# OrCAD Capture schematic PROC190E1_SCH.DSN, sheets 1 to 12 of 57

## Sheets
1 35. Ethernet PHY PWR SUPPLY: size C; title: ETHERNET PHY POWER SUPPLY; rev: E1
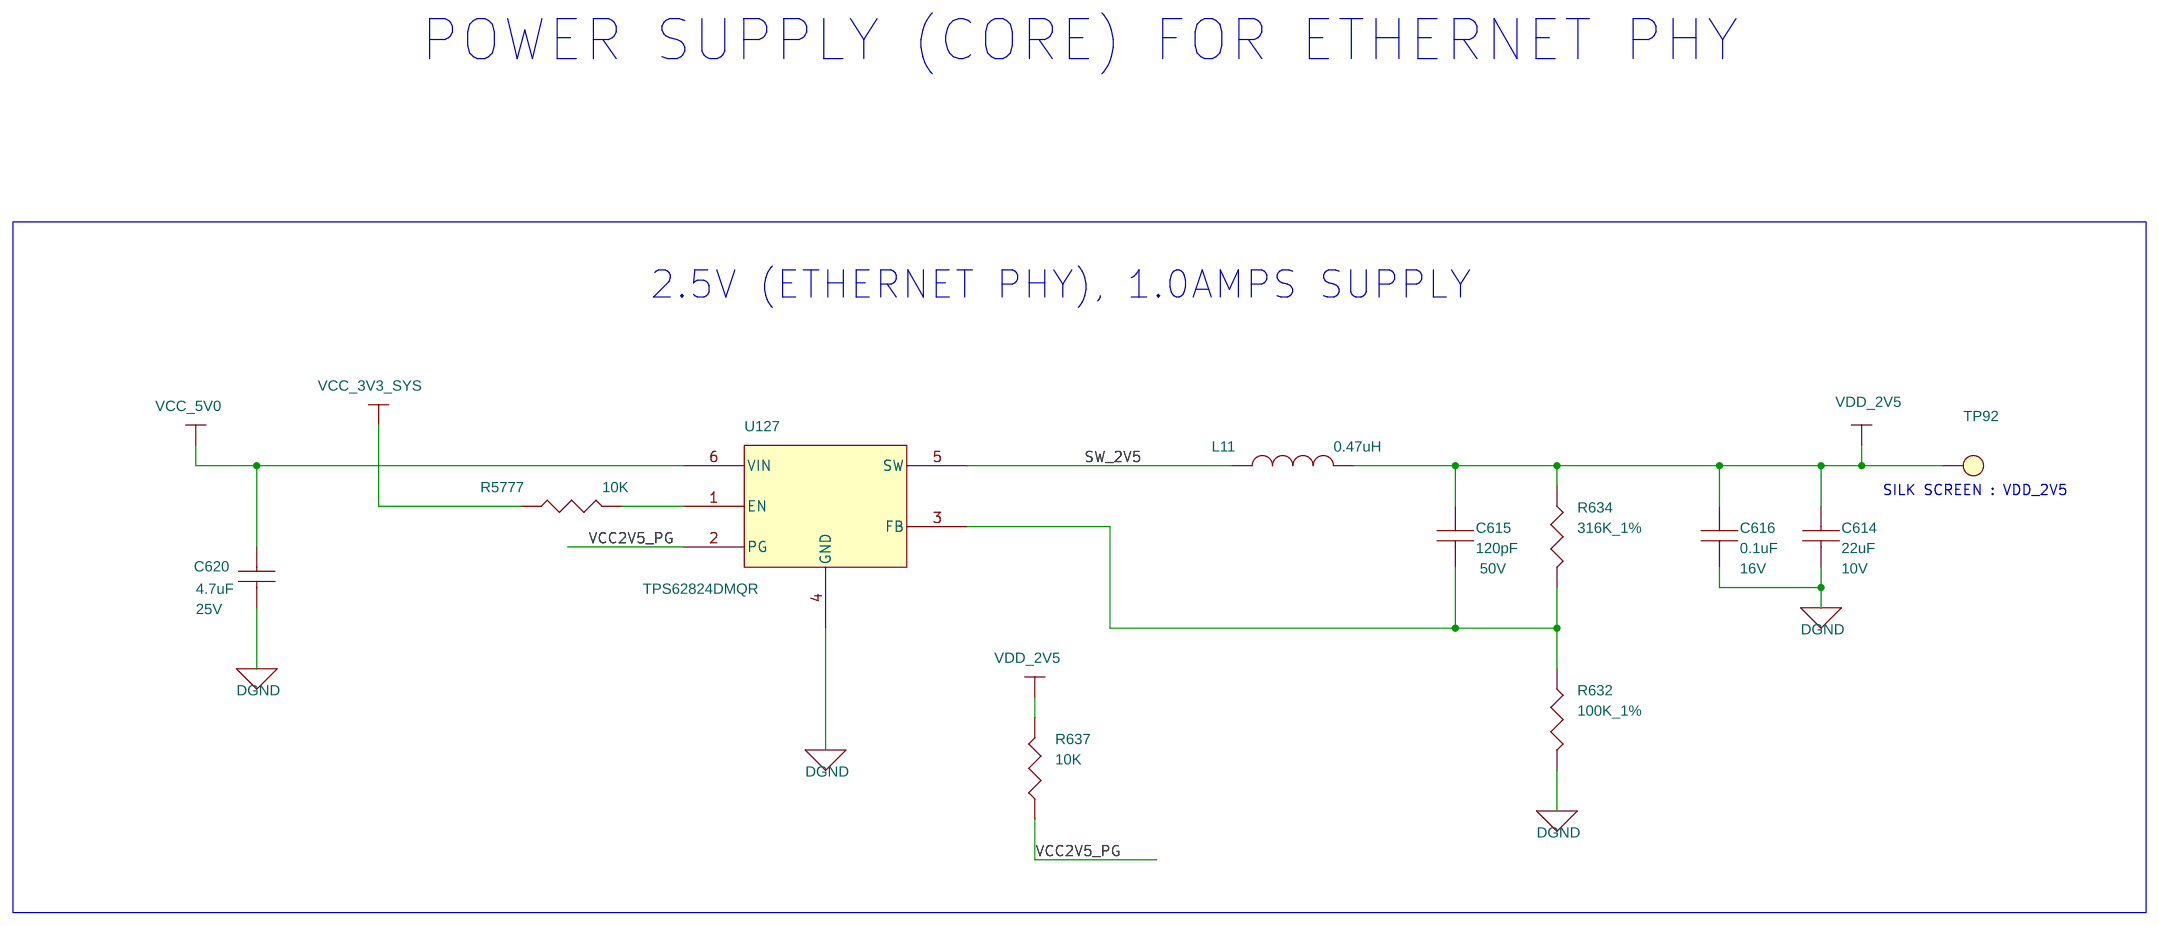
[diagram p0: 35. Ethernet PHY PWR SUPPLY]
2 26. MMC0 INTERFACE SELECTION: size C; title: MMC0 INTERFACE
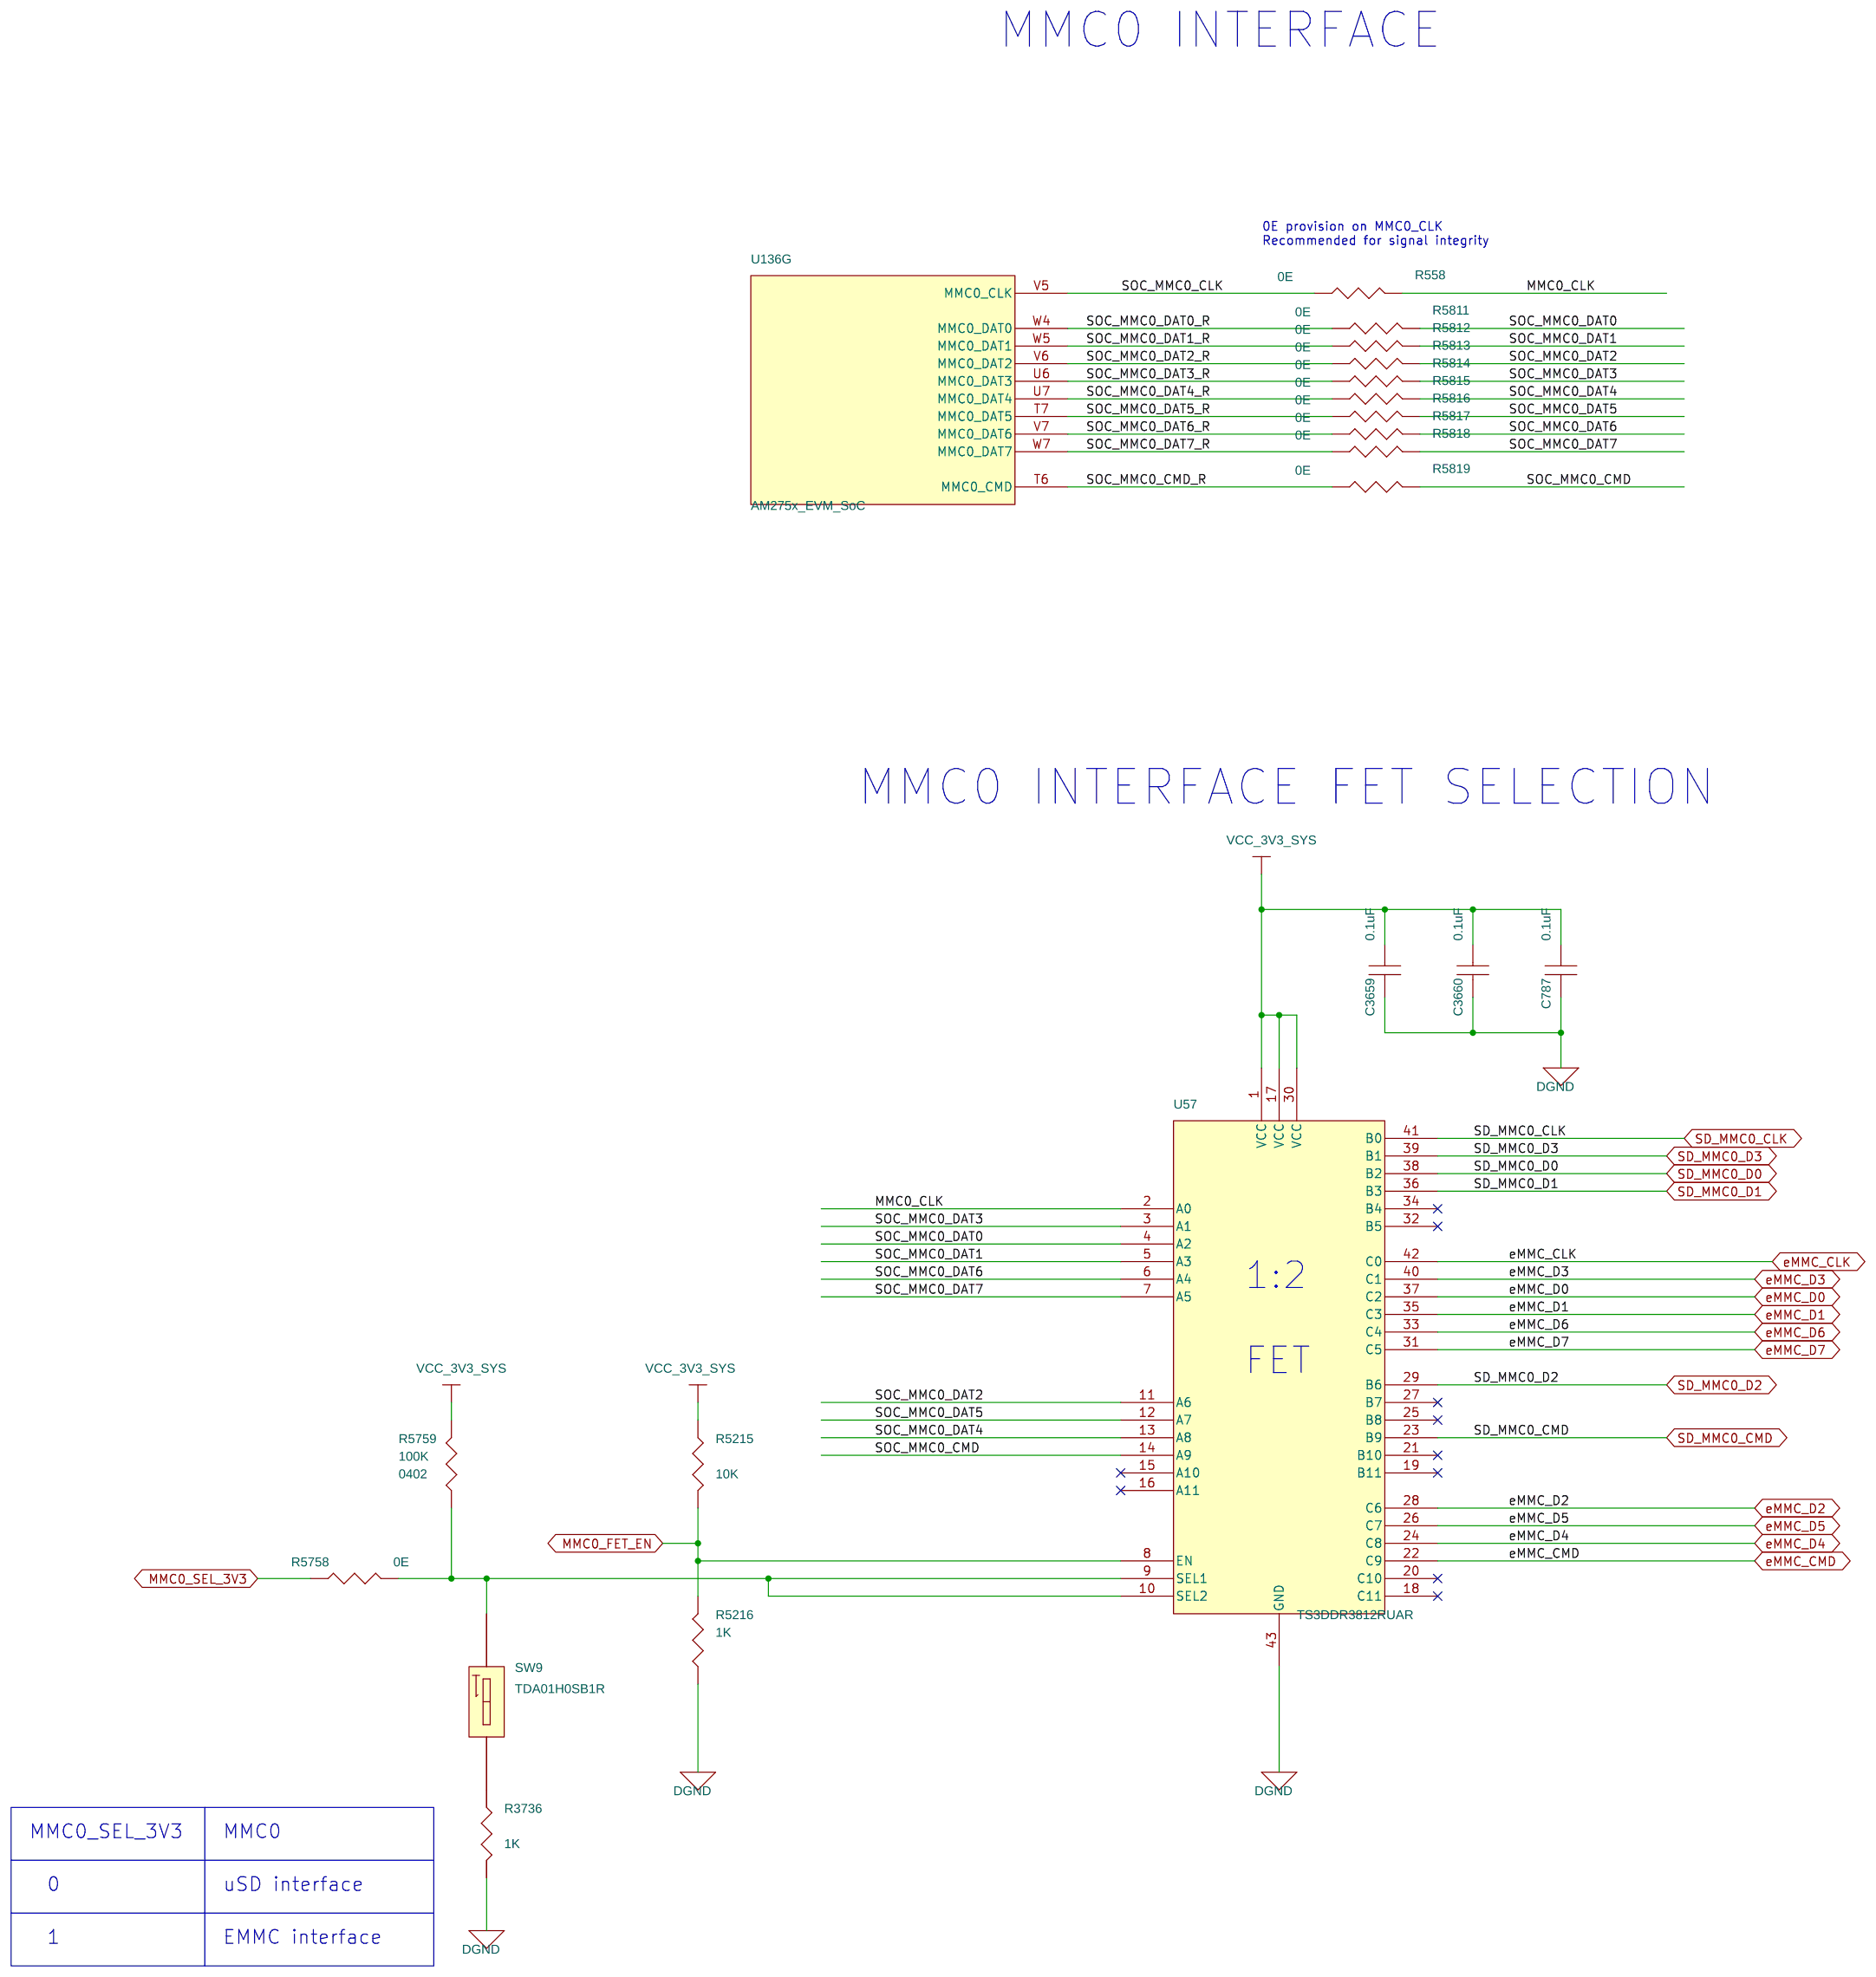
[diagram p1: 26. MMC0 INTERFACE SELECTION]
3 01. TABLE OF CONTENTS: title: TABLE OF CONTENTS
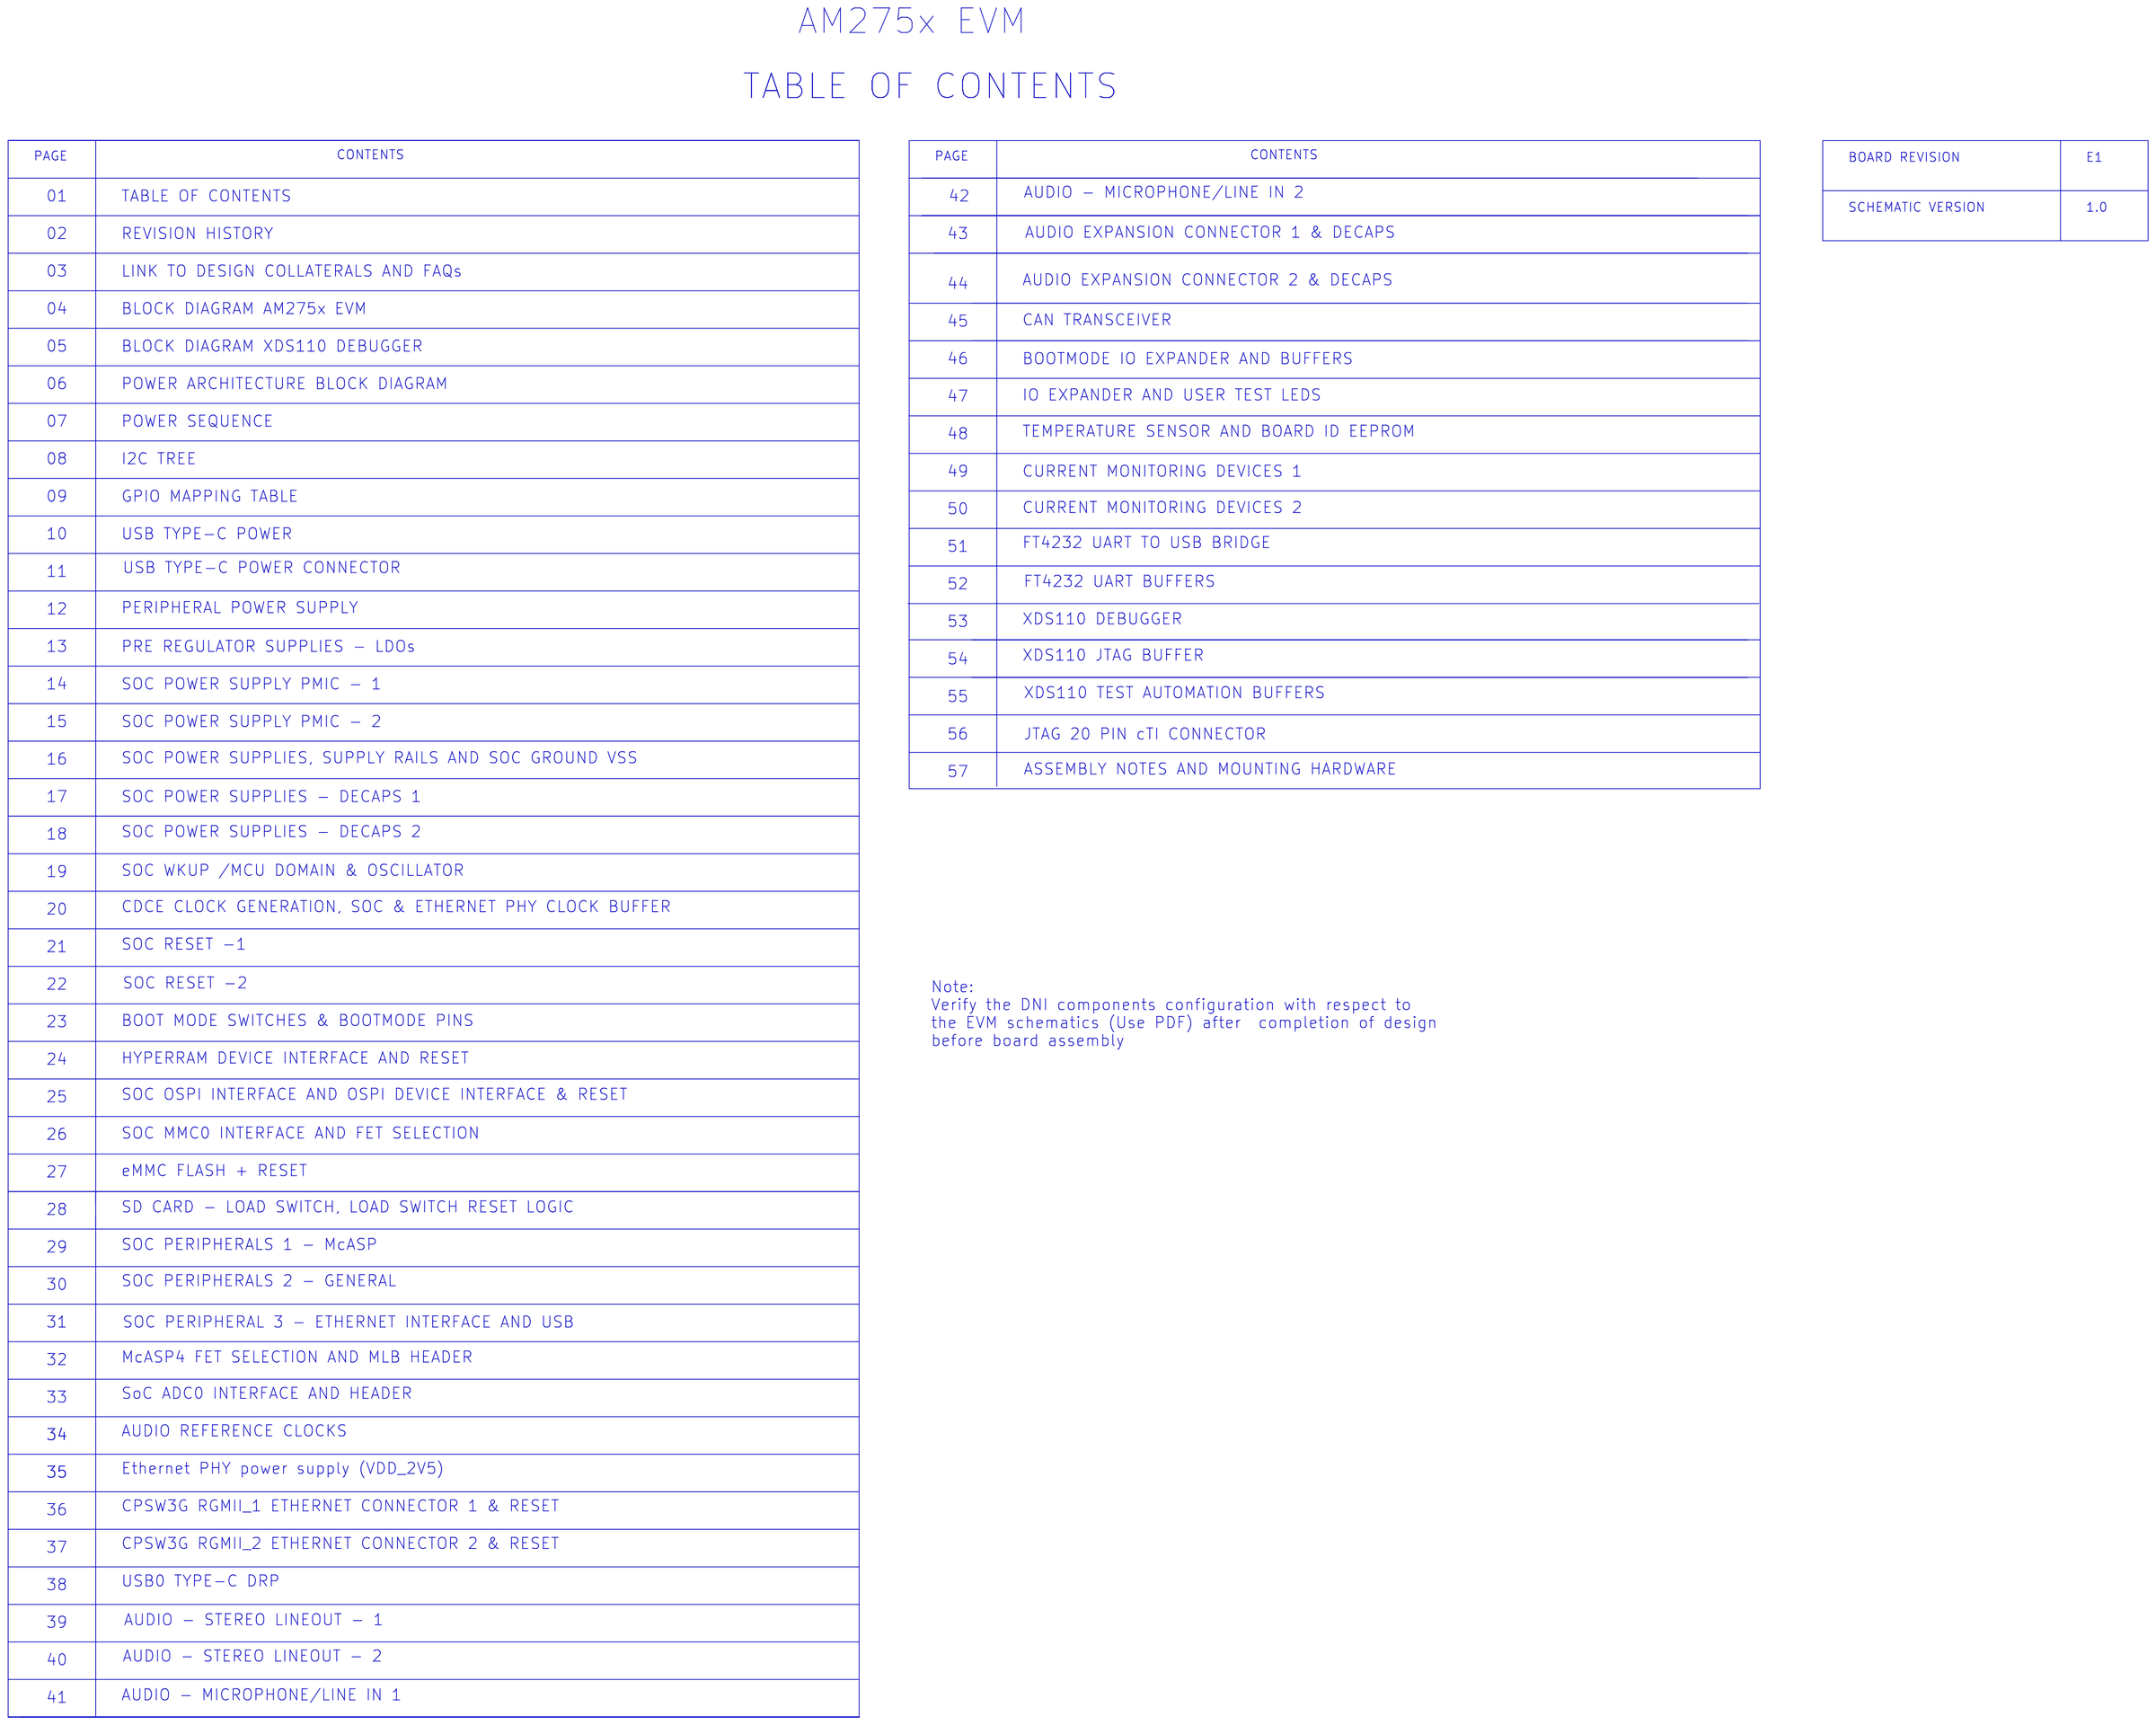
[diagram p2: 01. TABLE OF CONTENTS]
4 02. REVISION HISTORY: title: REVISION HISTORY
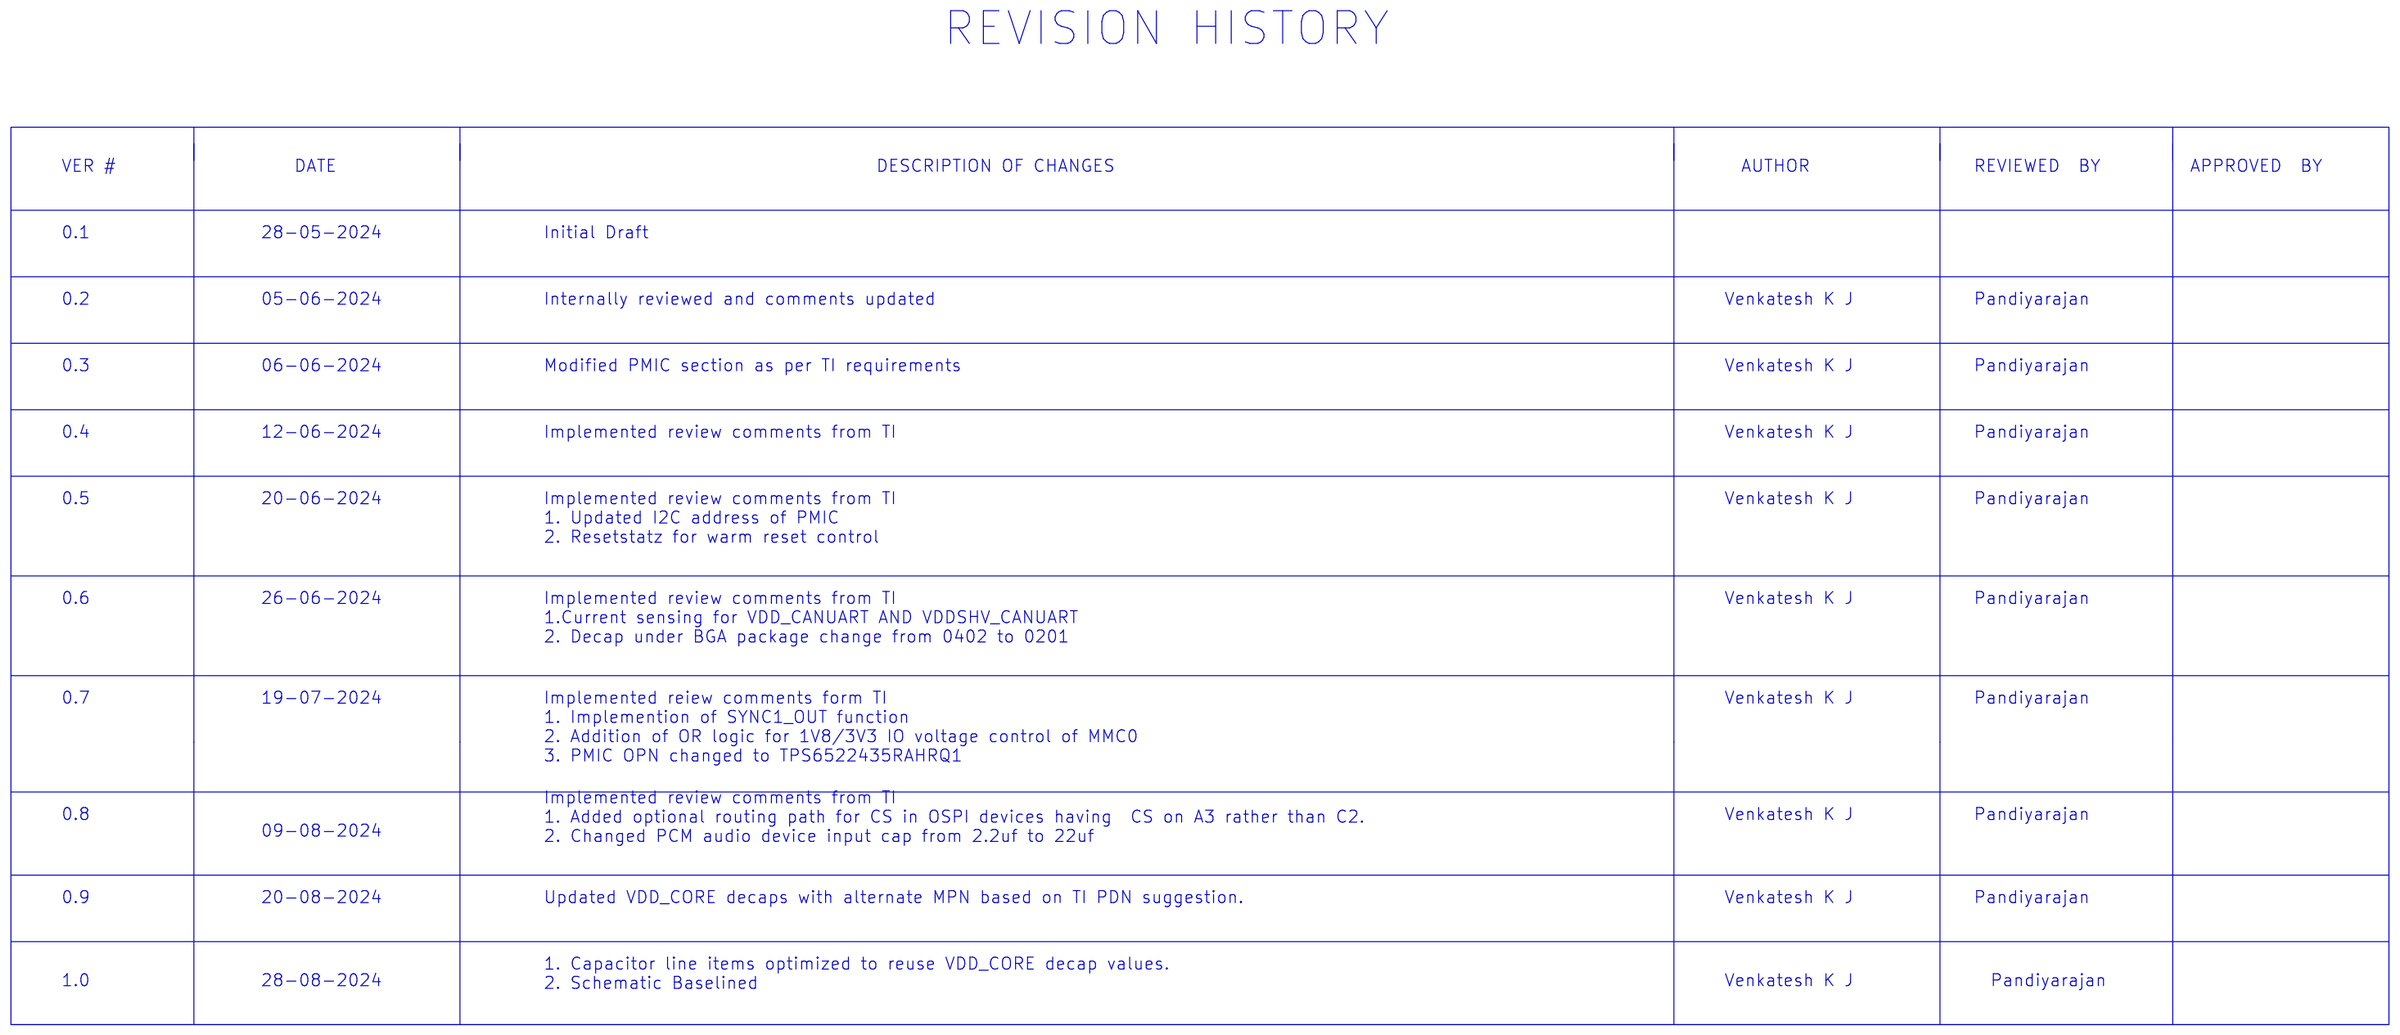
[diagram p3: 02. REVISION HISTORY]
5 03. KEY COLLATERAL REFERENCES: title: LINK TO DESIGN COLLATERALS
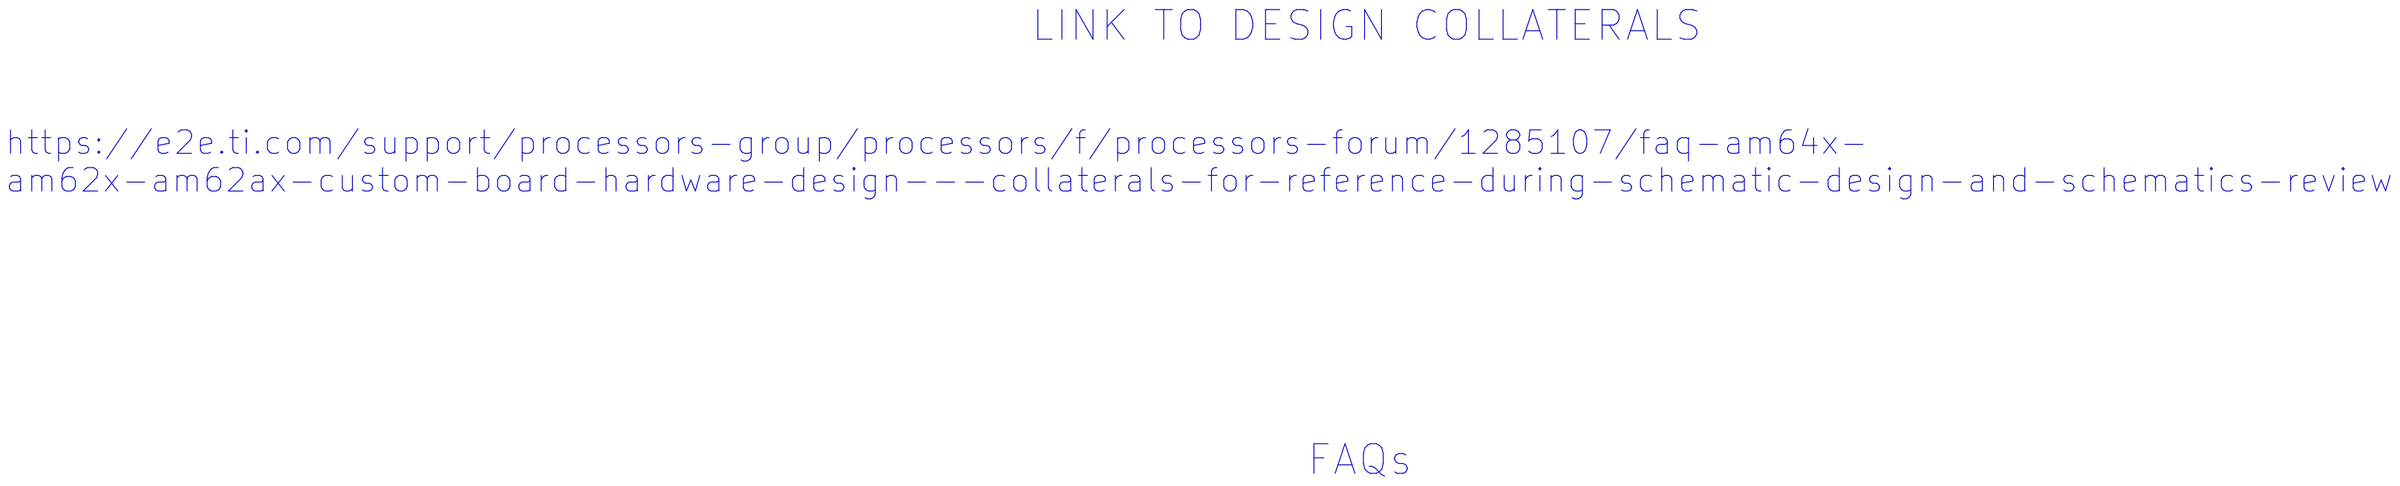
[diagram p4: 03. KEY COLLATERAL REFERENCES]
6 04. BLOCK DGM AM275 EVM: title: BLOCK DIAGRAM AM62D_ SKEVM
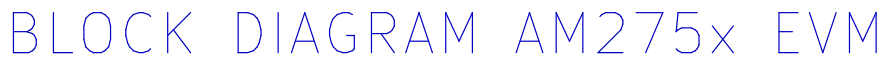
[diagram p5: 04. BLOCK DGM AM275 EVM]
7 05. BLOCK DIAGRAM_XDS110: title: BLOCK DIAGRAM_XDS110
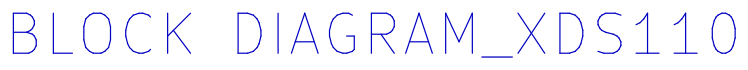
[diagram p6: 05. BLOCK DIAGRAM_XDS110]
8 06. POWER BLOCK DGM: title: POWER ARCHITECTURE BLOCK DIAGRAM
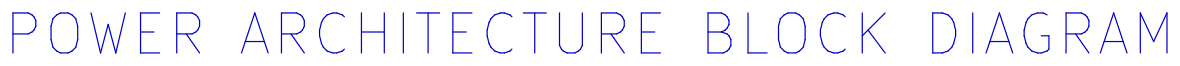
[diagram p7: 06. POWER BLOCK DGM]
9 07. POWER SEQUENCE: title: POWER SEQUENCE
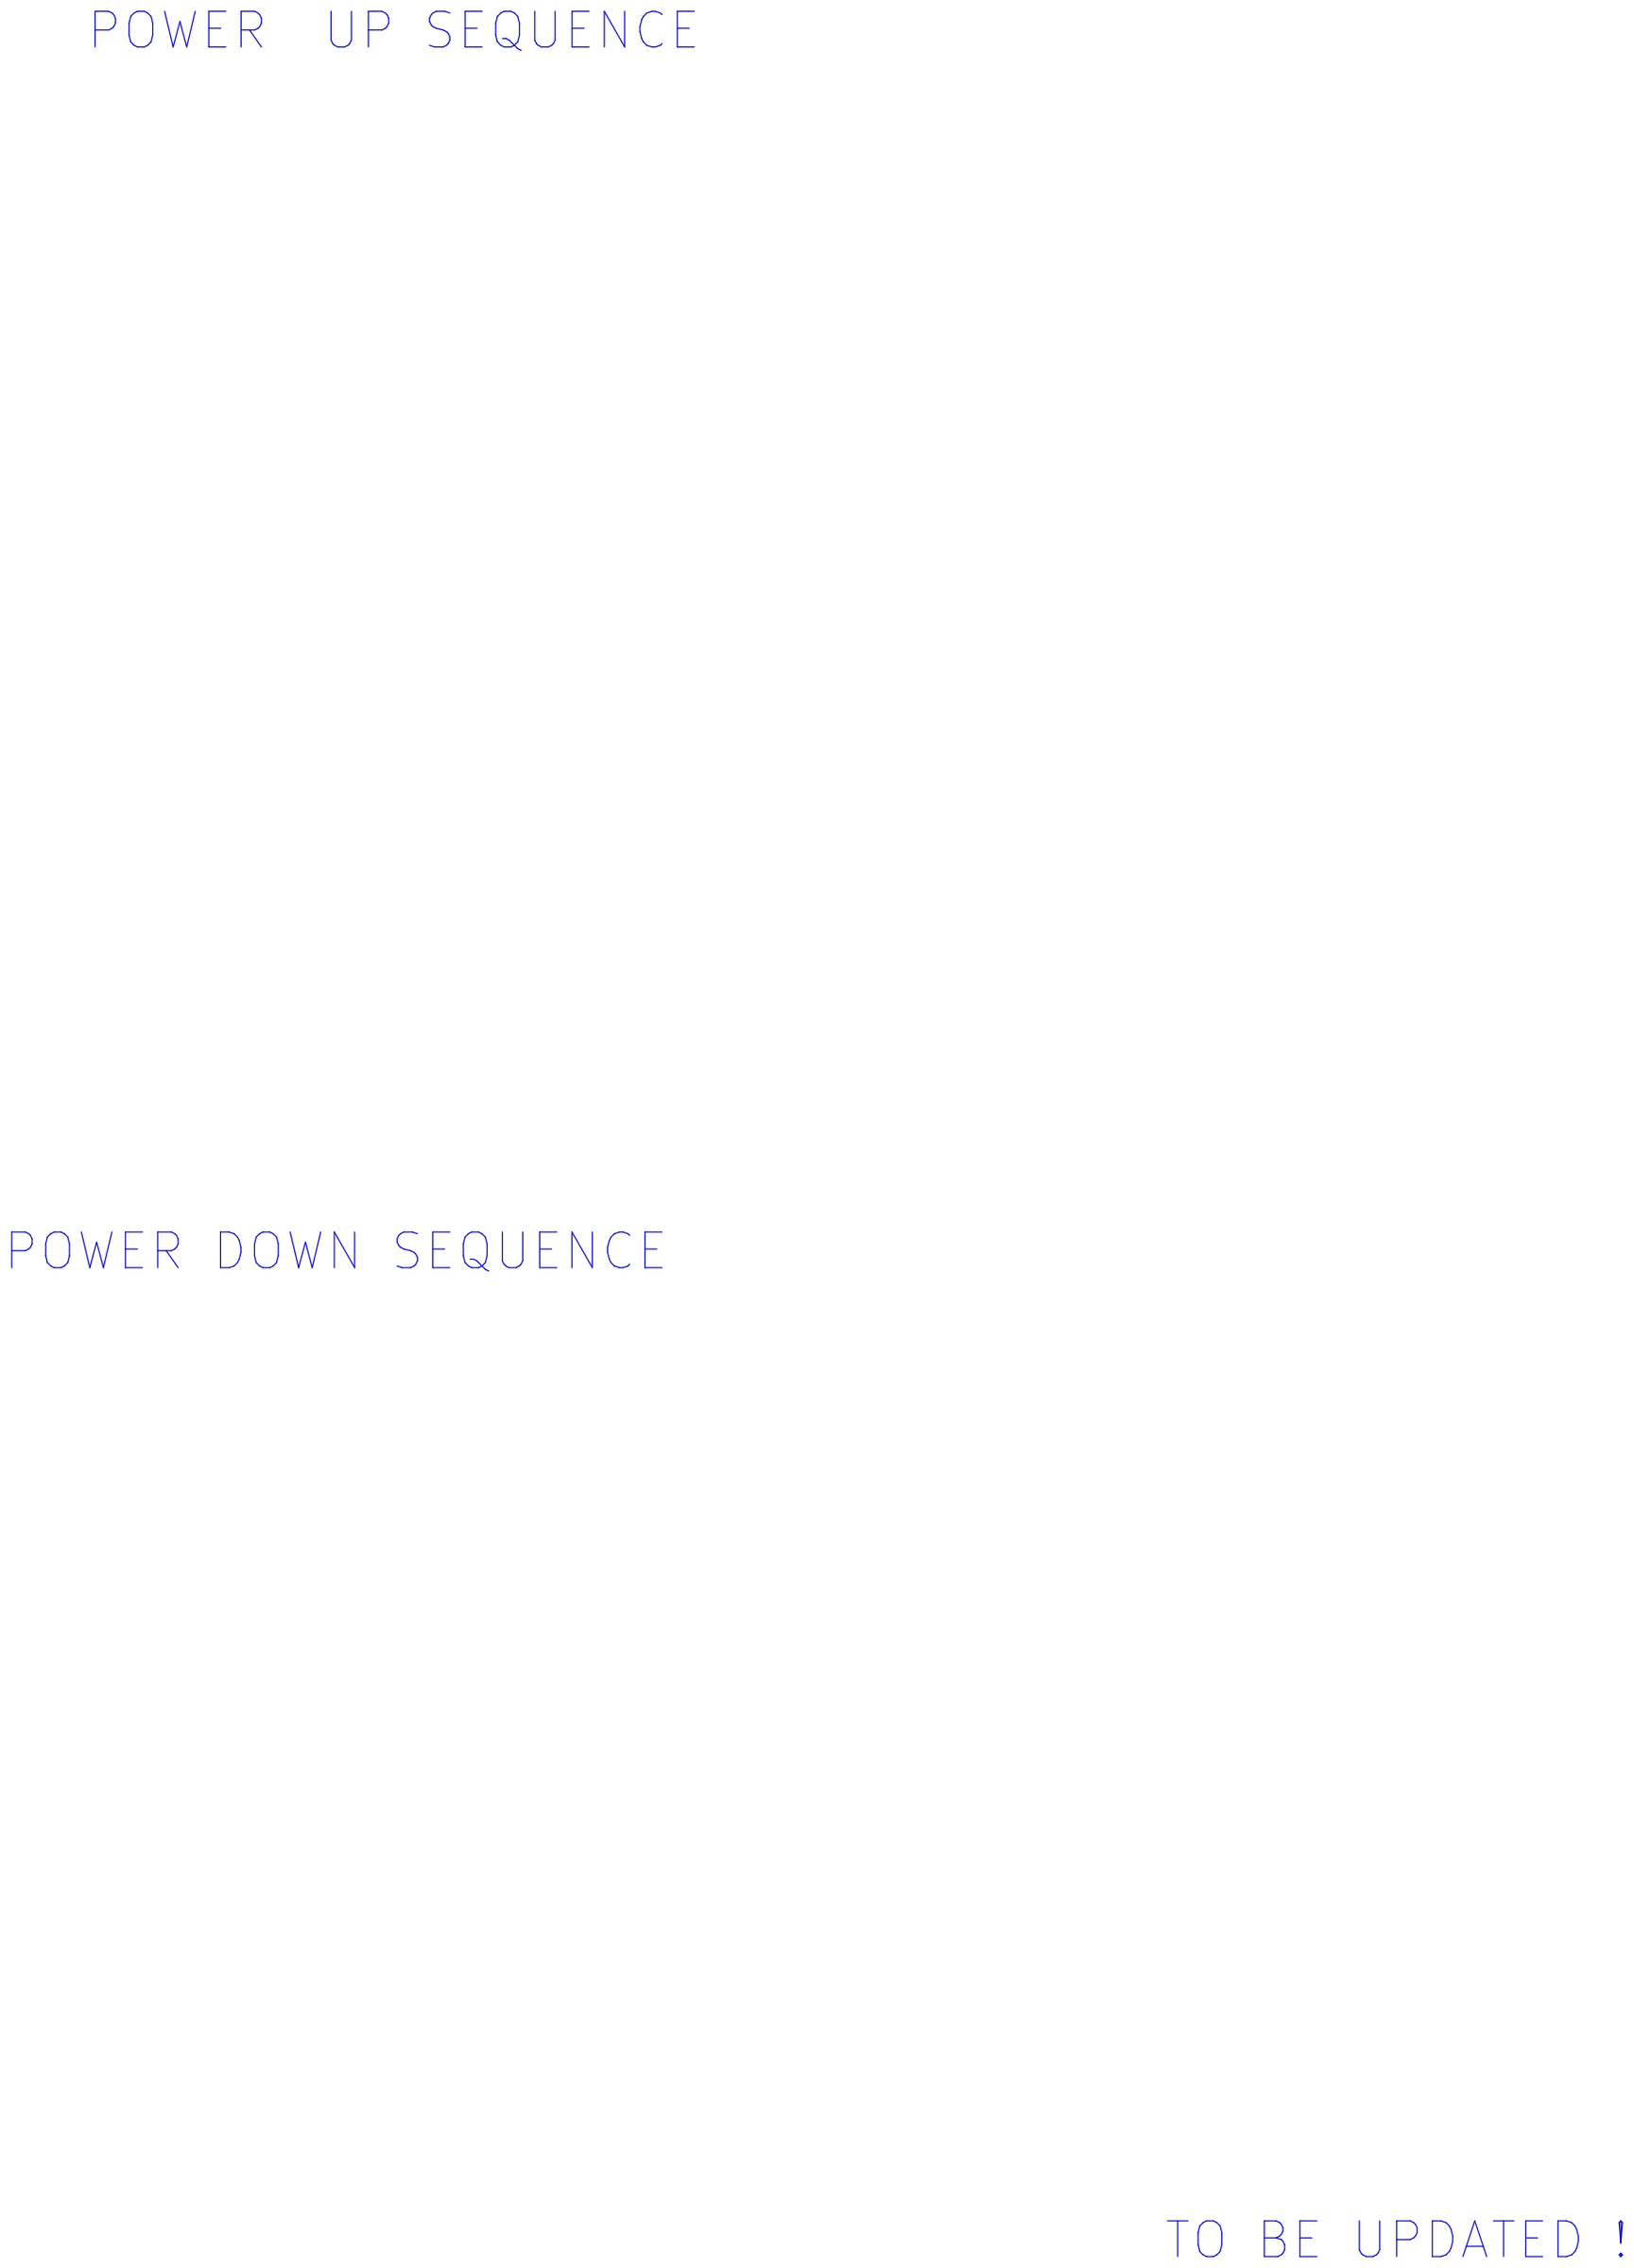
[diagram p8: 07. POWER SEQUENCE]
10 08. I2C TREE: title: I2C TREE
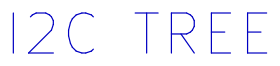
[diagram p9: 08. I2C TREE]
11 09. GPIO MAPPING TABLE: title: GPIO MAPPING TABLE
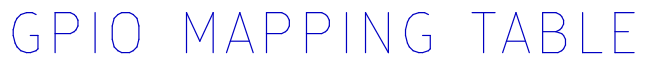
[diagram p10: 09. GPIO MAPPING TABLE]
12 10. USB TYPE-C POWER: size C; title: USB TYPE-C POWER
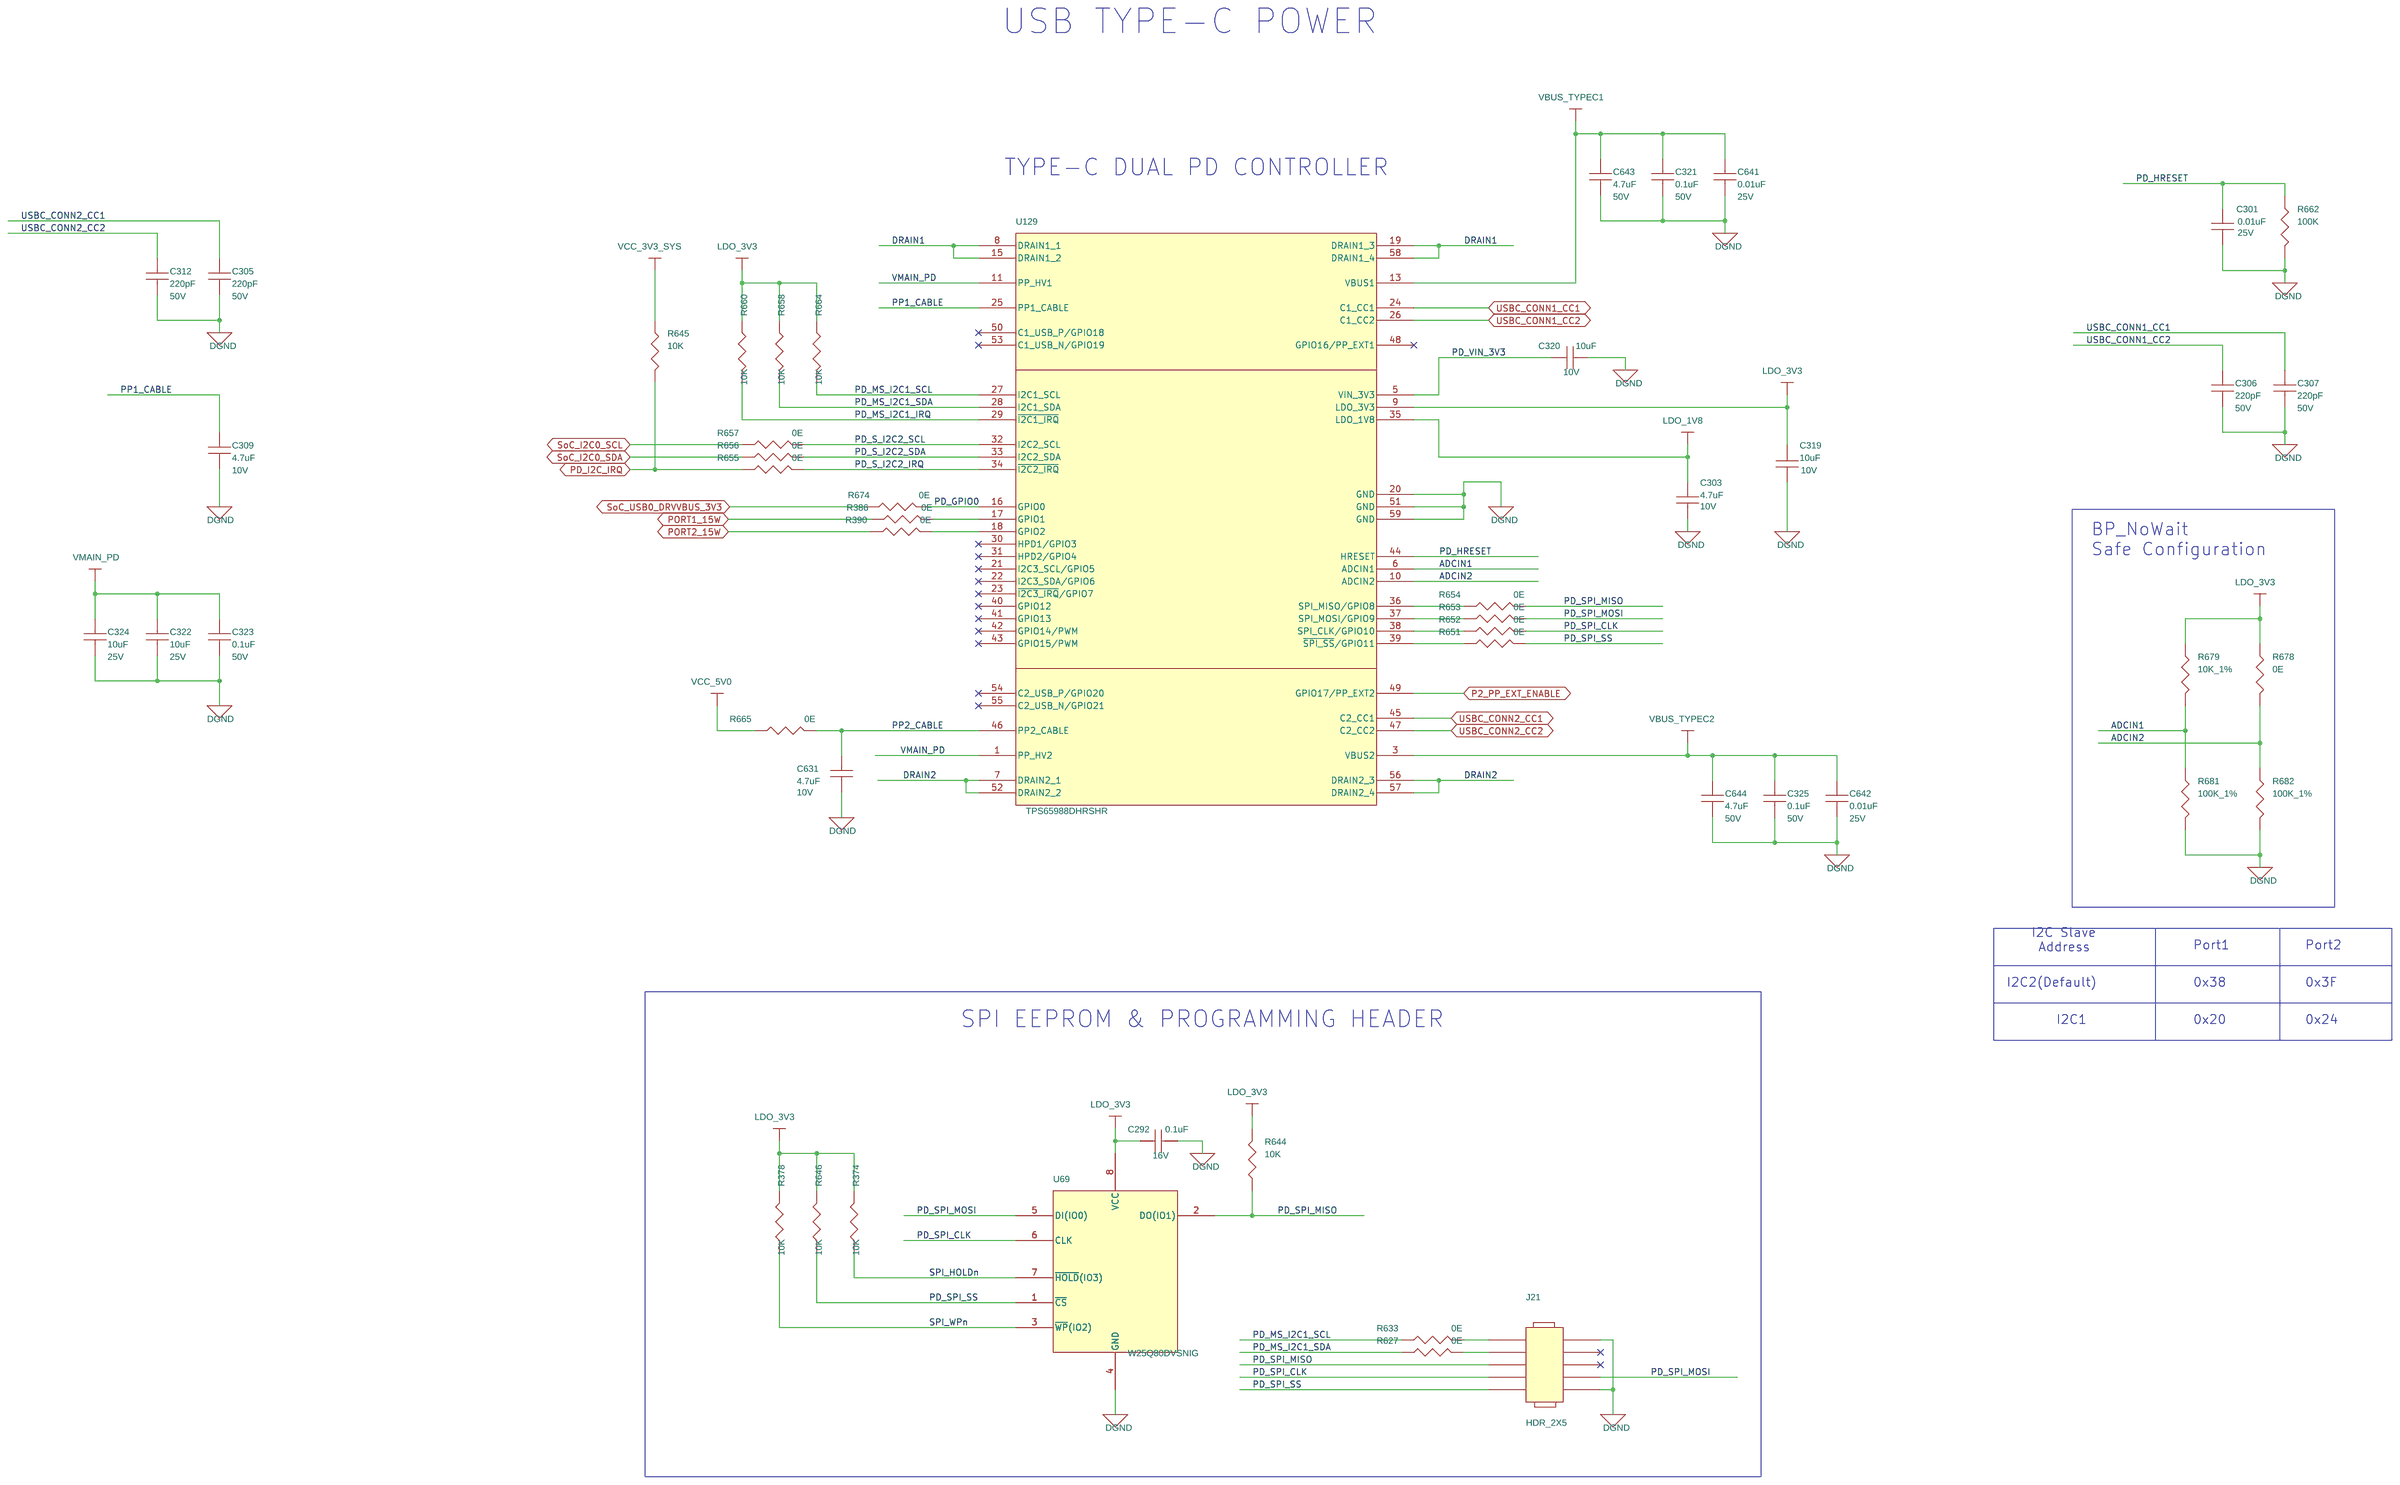
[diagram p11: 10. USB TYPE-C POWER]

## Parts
sheet 10. USB TYPE-C POWER
C292  0.1uF  [CAP0201_0-5]
C301  0.01uF  [CAP0201_0-5]
C303  4.7uF  [CAP0402_0-75]
C305  220pF  [CAP0402_0-75]
C306  220pF  [CAP0402_0-75]
C307  220pF  [CAP0402_0-75]
C309  4.7uF  [CAP0402_0-75]
C312  220pF  [CAP0402_0-75]
C319  10uF  [CAP0402_0-75]
C320  10uF  [CAP0402_0-75]
C321  0.1uF  [CAP0402_0-75]
C322  10uF  [CAP0603_1]
C323  0.1uF  [CAP0402_0-75]
C324  10uF  [CAP0603_1]
C325  0.1uF  [CAP0402_0-75]
C631  4.7uF  [CAP0402_0-75]
C641  0.01uF  [CAP0201_0-5]
C642  0.01uF  [CAP0201_0-5]
C643  4.7uF  [CAP0805_1-5]
C644  4.7uF  [CAP0805_1-5]
J21  HDR_2X5  [HDR_2X5_PEC05DAAN_S_T_8-6]
R374  10K  [RES0201_0-5]
R378  10K  [RES0201_0-5]
R386  0E  [RES0201_0-5]
R390  0E  [RES0201_0-5]
R627  0E  [RES0201_0-5]
R633  0E  [RES0201_0-5]
R644  10K  [RES0201_0-5]
R645  10K  [RES0201_0-5]
R646  10K  [RES0201_0-5]
R651  0E  [RES0201_0-5]
R652  0E  [RES0201_0-5]
R653  0E  [RES0201_0-5]
R654  0E  [RES0201_0-5]
R655  0E  [RES0201_0-5]
R656  0E  [RES0201_0-5]
R657  0E  [RES0201_0-5]
R658  10K  [RES0201_0-5]
R660  10K  [RES0201_0-5]
R662  100K  [RES0201_0-5]
R664  10K  [RES0201_0-5]
R665  0E  [RES0402_0-5]
R674  0E  [RES0201_0-5]
R678  0E  [RES0201_0-5]
R679  10K_1%  [RES0201_0-5]
R681  100K_1%  [RES0402_0-5]
R682  100K_1%  [RES0402_0-5]
U69  W25Q80DVSNIG  [SOIC8_1-8]
U129  TPS65988DHRSHR  [VQFN56_TPS65987D_280X280_1]
sheet 19. SOC WKUP & OSC
U136  AM275x_EVM_SoC  [BGA361_31-49_630X630_1-5]  (sections A,B,C,D,E,F,G,H,I,J,K,L,M,N)
sheet 26. MMC0 INTERFACE SELECTION
C787  0.1uF  [CAP0402_0-75]
C3659  0.1uF  [CAP0402_0-75]
C3660  0.1uF  [CAP0402_0-75]
R558  0E  [RES0402_0-5]
R3736  1K  [RES0201_0-5]
R5215  10K  [RES0201_0-5]
R5216  1K  [RES0201_0-5]
R5758  0E  [RES0201_0-5]
R5759  100K  [RES0402_0-5]
R5811  0E  [RES0402_0-5]
R5812  0E  [RES0402_0-5]
R5813  0E  [RES0402_0-5]
R5814  0E  [RES0402_0-5]
R5815  0E  [RES0402_0-5]
R5816  0E  [RES0402_0-5]
R5817  0E  [RES0402_0-5]
R5818  0E  [RES0402_0-5]
R5819  0E  [RES0402_0-5]
SW9  TDA01H0SB1R  [SW_TDA01H0S_240X90_SMD_2-3]
U57  TS3DDR3812RUAR  [TQFN42_19-68_140X360_0-8]
sheet 35. Ethernet PHY PWR SUPPLY
C614  22uF  [CAP0603_1]
C615  120pF  [CAP0201_0-5]
C616  0.1uF  [CAP0201_0-5]
C620  4.7uF  [CAP0603_1]
L11  0.47uH  [IND0806_1-2]
R632  100K_1%  [RES0402_0-5]
R634  316K_1%  [RES0402_0-5]
R637  10K  [RES0201_0-5]
R5777  10K  [RES0201_0-5]
TP92  TP20_SMD  [TP20_SMD]
U127  TPS62824DMQR  [VSONHR6_TPS62826_60X60_1]

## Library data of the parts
C292 C616 = CAP: CAP CERAMIC 0.1uF 16V 10% X7S AUTO 0201; Chkd/date: MANIRAJA/110321; Crtd /date: ALVY/110321; Custom_Duty: 15%; Customs_HS_Code: 85322990; Distributor_name: DIGIKEY; Distributor_part_number: 490-GRT033C71C104KE01DTR-ND; Footprint Path: Y:\MIS_DATABASE\Library\ALTIUM_TOOL\PCB_FOOTPRINTS\Altium_Footprint_Lib.PcbLib; Height: 0.33MM; Library Path: Y:\MIS_DATABASE\Library\ALTIUM_TOOL\SCHEMATICS_PARTS\MS_DISCRETE_Library.schlib; Mfr_name: MURATA; Mfr_part_number: GRT033C71C104KE01D; Mistral Part No: 120021030007-R; Package: 0201; Part_type: CAPACITORS\CERAMIC; Project: J7ES_SK_BRD; RoHS: RoHS; Temperature: -55°C+125°C; Tolerance: 10%; Voltage: 16V; Wattage: NA; Weight: 330mg; Datasheet: Y:\MIS_DATABASE\DATASHEETS\CAPACITORS\GRT033C71C104KE01.PDF
C301 C641 C642 = CAP: CAP CERAMIC 0.01uF 25V 10% X5R AUTO 0201; Chkd/date: MANIRAJA/311221; Crtd /date: ALVY/301221; Custom_Duty: 15%; Customs_HS_Code: 85322990; Distributor_name: MOUSER; Distributor_part_number: 81-GRT033R61E103KE1D; Footprint Path: Y:\MIS_DATABASE\Library\ALTIUM_TOOL\PCB_FOOTPRINTS\Altium_Footprint_Lib.PcbLib; Height: 0.33MM; Library Path: Y:\MIS_DATABASE\Library\ALTIUM_TOOL\SCHEMATICS_PARTS\MS_DISCRETE_Library.schlib; Mfr_name: MURATA; Mfr_part_number: GRT033R61E103KE01D; Mistral Part No: 120021120019-R; Package: 0201; Part_type: CAPACITORS\CERAMIC; Project: AM62Q_SKEVM_BRD; RoHS: RoHS; Temperature: -55°C+85°C; Tolerance: 10%; Voltage: 25V; Wattage: NA; Weight: 0.33mg; Datasheet: Y:\MIS_DATABASE\DATASHEETS\CAPACITORS\GRT033R61E103KE01.PDF
C303 C309 C631 = CAP: CAP CERAMIC 4.7uF 10V 20% X5R AUTO 0402; Chkd/date: MANIRAJA/250221; Crtd /date: ALVY/240221; Custom_Duty: 15%; Customs_HS_Code: 85322990; Distributor_name: MOUSER; Distributor_part_number: 81-GRT155R61A475ME13; Footprint Path: Y:\MIS_DATABASE\Library\ALTIUM_TOOL\PCB_FOOTPRINTS\Altium_Footprint_Lib.PcbLib; Height: 0.65MM; Library Path: Y:\MIS_DATABASE\Library\ALTIUM_TOOL\SCHEMATICS_PARTS\MS_DISCRETE_Library.schlib; Mfr_name: MURATA; Mfr_part_number: GRT155R61A475ME13D; Mistral Part No: 120021020032-R; Package: 0402; Part_type: CAPACITORS\CERAMIC; Project: TI_DRA821 SK EVM BRD; RoHS: RoHS; Temperature: -55°C+85°C; Tolerance: 20%; Voltage: 10V; Wattage: NA; Weight: 1.5mg; Datasheet: Y:\MIS_DATABASE\DATASHEETS\CAPACITORS\GRT155R61A475ME13.PDF
C305-C307 C312 = CAP: CAP CERAMIC 220pF 50V 5% C0G(NP0) AUTO 0402; Chkd/date: PRADEEP/130623; Crtd /date: PRADEEP/130623; Custom_Duty: 15%; Customs_HS_Code: 85322990; Distributor_name: NA; Distributor_part_number: NA; Footprint Path: Y:\MIS_DATABASE\Library\ALTIUM_TOOL\PCB_FOOTPRINTS\Altium_Footprint_Lib.PcbLib; Height: 0.55MM; Library Path: Y:\MIS_DATABASE\Library\ALTIUM_TOOL\SCHEMATICS_PARTS\MS_DISCRETE_Library.schlib; Mfr_name: MURATA; Mfr_part_number: GRT1555C1H221JA02; Mistral Part No: 120022060024-R; Package: 0402; Part_type: CAPACITORS\CERAMIC; Project: AM62P_SK; RoHS: RoHS; Temperature: -55°C+125°C; Tolerance: 5%; Voltage: 50V; Wattage: NA; Weight: 3.1mg; Datasheet: Y:\MIS_DATABASE\DATASHEETS\CAPACITORS\GRT1555C1H221JA02.PDF
C319 C320 = CAP: CAP CERAMIC 10uF 10V 20% X5R 0402; Chkd/date: PRADEEP/130623; Crtd /date: PRADEEP/130623; Custom_Duty: 15%; Customs_HS_Code: 85322990; Distributor_name: NA; Distributor_part_number: NA; Footprint Path: Y:\MIS_DATABASE\Library\ALTIUM_TOOL\PCB_FOOTPRINTS\Altium_Footprint_Lib.PcbLib; Height: 0.55MM; Library Path: Y:\MIS_DATABASE\Library\ALTIUM_TOOL\SCHEMATICS_PARTS\MS_DISCRETE_Library.schlib; Mfr_name: MURATA; Mfr_part_number: GRM155R61A106ME18; Mistral Part No: 120022060018-R; Package: 0402; Part_type: CAPACITORS\CERAMIC; Project: AM62P_SK; RoHS: RoHS; Temperature: -55°C+85°C; Tolerance: 20%; Voltage: 10V; Wattage: NA; Weight: 6mg; Datasheet: Y:\MIS_DATABASE\DATASHEETS\CAPACITORS\MURATA-GXX-SER_NOV17.PDF
C321 C323 C325 = CAP: CAP CERAMIC 0.1uF 50V 10% X7R AUTO 0402; Chkd/date: MANIRAJA/250221; Crtd /date: ALVY/240221; Custom_Duty: 15%; Customs_HS_Code: 85322990; Distributor_name: MOUSER; Distributor_part_number: 81-GRT155R71H104KE1D; Footprint Path: Y:\MIS_DATABASE\Library\ALTIUM_TOOL\PCB_FOOTPRINTS\Altium_Footprint_Lib.PcbLib; Height: 0.55MM; Library Path: Y:\MIS_DATABASE\Library\ALTIUM_TOOL\SCHEMATICS_PARTS\MS_DISCRETE_Library.schlib; Mfr_name: MURATA; Mfr_part_number: GRT155R71H104KE01D; Mistral Part No: 120019030005-R; Package: 0402; Part_type: CAPACITORS\CERAMIC; Project: TI_DRA821 SK EVM BRD; RoHS: RoHS; Temperature: -55°C+125°C; Tolerance: 10%; Voltage: 50V; Wattage: NA; Weight: NA; Datasheet: Y:\MIS_DATABASE\DATASHEETS\CAPACITORS\GRT155R71H104KE01.PDF
C322 C324 = CAP: CAP CERAMIC 10uF 25V 20% X5R AUTO 0603; Chkd/date: PRADEEP/130623; Crtd /date: PRADEEP/130623; Custom_Duty: 15%; Customs_HS_Code: 85322990; Distributor_name: NA; Distributor_part_number: NA; Footprint Path: Y:\MIS_DATABASE\Library\ALTIUM_TOOL\PCB_FOOTPRINTS\Altium_Footprint_Lib.PcbLib; Height: 1.00MM; Library Path: Y:\MIS_DATABASE\Library\ALTIUM_TOOL\SCHEMATICS_PARTS\MS_DISCRETE_Library.schlib; Mfr_name: MURATA; Mfr_part_number: GRT188R61E106ME13; Mistral Part No: 120022060023-R; Package: 0603; Part_type: CAPACITORS\CERAMIC; Project: AM62P_SK; RoHS: RoHS; Temperature: -55°C+85°C; Tolerance: 20%; Voltage: 25V; Wattage: NA; Weight: 2mg; Datasheet: Y:\MIS_DATABASE\DATASHEETS\CAPACITORS\GRT188R61E106ME13.PDF
C643 C644 = CAP: CAP CERAMIC 4.7uF 50V 10% X5R 0805; Chkd/date: VASANTHA/281216; Crtd /date: BAVISH/290711; Custom_Duty: 15%; Customs_HS_Code: 85322990; Distributor_name: DIGIKEY; Distributor_part_number: 445-5980-1-ND; Footprint Path: Y:\MIS_DATABASE\Library\ALTIUM_TOOL\PCB_FOOTPRINTS\Altium_Footprint_Lib.PcbLib; Height: 1.45MM; Library Path: Y:\MIS_DATABASE\Library\ALTIUM_TOOL\SCHEMATICS_PARTS\MS_DISCRETE_Library.schlib; Mfr_name: TDK CORPORATION; Mfr_part_number: C2012X5R1H475K; Mistral Part No: 120011070010-R; Package: 0805; Part_type: CAPACITORS\CERAMIC; Project: OMAPL1_PEC20; RoHS: RoHS; Temperature: -55°C+85°C; Tolerance: 10%; Voltage: 50V; Wattage: NA; Weight: 5.5mg; Datasheet: Y:\MIS_DATABASE\DATASHEETS\CAPACITORS\TDK_C-SERIES.PDF
J21 = HEADER_5X2: CON HDR 2X5 2.54MM PITCH ST TH; Chkd/date: MANIRAJA/060821; Crtd /date: ALVY/060821; Custom_Duty: 24%; Customs_HS_Code: 85369090; Distributor_name: DIGIKEY; Distributor_part_number: S2012E-05-ND; Footprint Path: Y:\MIS_DATABASE\Library\ALTIUM_TOOL\PCB_FOOTPRINTS\Altium_Footprint_Lib.PcbLib; Height: 8.58MM; Library Path: Y:\MIS_DATABASE\Library\ALTIUM_TOOL\SCHEMATICS_PARTS\MS_CONNECTOR_Library.schlib; Mfr_name: SULLINS CONNECTOR; Mfr_part_number: PEC05DAAN; Mistral Part No: 150021080010-R; Package: THRU-HOLE; Part_type: CONNECTOR\HEADERS; Project: TI_AM335x SK_BRD; RoHS: RoHS; Temperature: -65°C+125°C; Tolerance: NA; Voltage: NA; Wattage: NA; Weight: NA; Datasheet: Y:\MIS_DATABASE\DATASHEETS\CONNECTORS\XXCXXDXXN.PDF
R374 R378 R637 R644-R646 R658 R660 R664 R5215 R5777 = RESISTOR: RES 10K 1/20W 5% 0201; Chkd/date: MANIRAJA/050517; Crtd /date: MANIRAJA/050517; Custom_Duty: 15%; Customs_HS_Code: 85332119; Distributor_name: DIGIKEY; Distributor_part_number: 311-10KNCT-ND; Footprint Path: Y:\MIS_DATABASE\Library\ALTIUM_TOOL\PCB_FOOTPRINTS\Altium_Footprint_Lib.PcbLib; Height: 0.26MM; Library Path: Y:\MIS_DATABASE\Library\ALTIUM_TOOL\SCHEMATICS_PARTS\MS_DISCRETE_Library.schlib; Mfr_name: YAGEO AMERICA; Mfr_part_number: RC0201JR-0710KL; Mistral Part No: 110010070051-R; Package: 0201; Part_type: RESISTORS\FIXED; Project: GOLDEN-I LITE; RoHS: RoHS; Temperature: -55°C+125°C; Tolerance: 5%; Voltage: NA; Wattage: 1/20W; Weight: 0.17mg; Datasheet: Y:\MIS_DATABASE\DATASHEETS\RESISTORS\RCXXXXL-SER_MAR18.PDF
R386 R390 R627 R633 R651-R657 R674 R5758 = RESISTOR: RES 0E 1/20W 5% 0201; Chkd/date: NAVEED/301214; Crtd /date: MUDDU/120710; Custom_Duty: 15%; Customs_HS_Code: 85332119; Distributor_name: DIGIKEY; Distributor_part_number: 311-0.0NCT-ND; Footprint Path: Y:\MIS_DATABASE\Library\ALTIUM_TOOL\PCB_FOOTPRINTS\Altium_Footprint_Lib.PcbLib; Height: 0.26MM; Library Path: Y:\MIS_DATABASE\Library\ALTIUM_TOOL\SCHEMATICS_PARTS\MS_DISCRETE_Library.schlib; Mfr_name: YAGEO AMERICA; Mfr_part_number: RC0201JR-070RL; Mistral Part No: 110010070067-R; Package: 0201; Part_type: RESISTORS\FIXED; Project: PB_BUGBASE; RoHS: RoHS; Temperature: -55°C+125°C; Tolerance: 5%; Voltage: NA; Wattage: 1/20W; Weight: 0.17mg; Datasheet: Y:\MIS_DATABASE\DATASHEETS\RESISTORS\RCXXXXL-SER_MAR18.PDF
R662 = RESISTOR: RES 100K 1/20W 5% 0201; Chkd/date: MANIRAJA/050517; Crtd /date: MANIRAJA/050517; Custom_Duty: 15%; Customs_HS_Code: 85332119; Distributor_name: DIGIKEY; Distributor_part_number: 311-100KNCT-ND; Footprint Path: Y:\MIS_DATABASE\Library\ALTIUM_TOOL\PCB_FOOTPRINTS\Altium_Footprint_Lib.PcbLib; Height: 0.26MM; Library Path: Y:\MIS_DATABASE\Library\ALTIUM_TOOL\SCHEMATICS_PARTS\MS_DISCRETE_Library.schlib; Mfr_name: YAGEO AMERICA; Mfr_part_number: RC0201JR-07100KL; Mistral Part No: 110009030176-R; Package: 0201; Part_type: RESISTORS\FIXED; Project: GOLDEN-I LITE; RoHS: RoHS; Temperature: -55°C+125°C; Tolerance: 5%; Voltage: NA; Wattage: 1/20W; Weight: 0.17mg; Datasheet: Y:\MIS_DATABASE\DATASHEETS\RESISTORS\RCXXXXL-SER_MAR18.PDF
R665 = RESISTOR: RES 0E 1/10W JUMPER 0402; Chkd/date: VASANTHA/061216; Crtd /date: NAVEED/201014; Custom_Duty: 15%; Customs_HS_Code: 85332119; Distributor_name: DIGIKEY; Distributor_part_number: P0.0JCT-ND; Footprint Path: Y:\MIS_DATABASE\Library\ALTIUM_TOOL\PCB_FOOTPRINTS\Altium_Footprint_Lib.PcbLib; Height: 0.40MM; IBISSP_MODLES: VALUE REPEATING 2 TIME; Library Path: Y:\MIS_DATABASE\Library\ALTIUM_TOOL\SCHEMATICS_PARTS\MS_DISCRETE_Library.schlib; Mfr_name: PANASONIC-ECG; Mfr_part_number: ERJ-2GE0R00X; Mistral Part No: 110018030052-R; Package: 0402; Part_type: RESISTORS\FIXED; Project: AEGIS POM; RoHS: RoHS; Temperature: -55°C+155°C; Tolerance: NA; Voltage: NA; Wattage: 1/10W; Weight: 0.8mg; Datasheet: Y:\MIS_DATABASE\DATASHEETS\RESISTORS\PAN-ERJSER_NOV17.PDF
R678 = RESISTOR: RES 0E 1/20W JUMPER 0201; Chkd/date: VASANTHA/061216; Crtd /date: MAZHAR/040505; Custom_Duty: 15%; Customs_HS_Code: 85332119; Distributor_name: DIGIKEY; Distributor_part_number: P0.0AGCT-ND; Footprint Path: Y:\MIS_DATABASE\Library\ALTIUM_TOOL\PCB_FOOTPRINTS\Altium_Footprint_Lib.PcbLib; Height: 0.26MM; Library Path: Y:\MIS_DATABASE\Library\ALTIUM_TOOL\SCHEMATICS_PARTS\MS_DISCRETE_Library.schlib; Mfr_name: PANASONIC-ECG; Mfr_part_number: ERJ-1GE0R00C; Mistral Part No: 110009030078-R; Package: 0201; Part_type: RESISTORS\FIXED; Project: HS100RD; RoHS: RoHS; Temperature: -55°C+125°C; Tolerance: NA; Voltage: NA; Wattage: 1/20W; Weight: 0.15mg; Datasheet: Y:\MIS_DATABASE\DATASHEETS\RESISTORS\PAN-ERJXGE-FEB06.PDF
R679 = RESISTOR: RES 10K 1/20W 1% 0201; Chkd/date: VASANTHA/270117; Crtd /date: MANIRAJA/270117; Custom_Duty: 15%; Customs_HS_Code: 85332119; Distributor_name: DIGIKEY; Distributor_part_number: 311-10.0KMCT-ND; Footprint Path: Y:\MIS_DATABASE\Library\ALTIUM_TOOL\PCB_FOOTPRINTS\Altium_Footprint_Lib.PcbLib; Height: 0.26MM; Library Path: Y:\MIS_DATABASE\Library\ALTIUM_TOOL\SCHEMATICS_PARTS\MS_DISCRETE_Library.schlib; Mfr_name: YAGEO AMERICA; Mfr_part_number: RC0201FR-0710KL; Mistral Part No: 110011040018-R; Package: 0201; Part_type: RESISTORS\FIXED; Project: GOLDEN-I LITE; RoHS: RoHS; Temperature: -55°C+125°C; Tolerance: 1%; Voltage: NA; Wattage: 1/20W; Weight: 0.17mg; Datasheet: Y:\MIS_DATABASE\DATASHEETS\RESISTORS\RCXXXXL-SER_MAR18.PDF
R632 R681 R682 = RESISTOR: RES 100K 1/10W 1% 0402; Chkd/date: VASANTHA/201216; Crtd /date: MAZHAR/130306; Custom_Duty: 15%; Customs_HS_Code: 85332119; Distributor_name: DIGIKEY; Distributor_part_number: P100KLCT-ND; Footprint Path: Y:\MIS_DATABASE\Library\ALTIUM_TOOL\PCB_FOOTPRINTS\Altium_Footprint_Lib.PcbLib; Height: 0.40MM; Library Path: Y:\MIS_DATABASE\Library\ALTIUM_TOOL\SCHEMATICS_PARTS\MS_DISCRETE_Library.schlib; Mfr_name: PANASONIC-ECG; Mfr_part_number: ERJ-2RKF1003X; Mistral Part No: 110009030187-R; Package: 0402; Part_type: RESISTORS\FIXED; Project: J32; RoHS: RoHS; Temperature: -55°C+155°C; Tolerance: 1%; Voltage: NA; Wattage: 1/10W; Weight: 0.8mg; Datasheet: Y:\MIS_DATABASE\DATASHEETS\RESISTORS\PAN-ERJSER_NOV17.PDF
U69 = W25Q80BWSNIG_SOIC8: IC SERIAL FLASH MEMORY SOIC8; Chkd/date: VASANTHA/150217; Crtd /date: MANIRAJA/150217; Custom_Duty: 15%; Customs_HS_Code: 85423100; Distributor_name: DIGIKEY; Distributor_part_number: W25Q80DVSNIG CT-ND; Height: 1.75MM; Mfr_name: WINBOND; Mfr_part_number: W25Q80DVSNIG-TR; Mistral Part No: 141117020010-R; Package: SOIC8; Part_type: ICS\DIGITAL\MEMORY; Project: SD820_NANO_SOM; RoHS: RoHS; Temperature: -40°C+85°C; Tolerance: NA; Voltage: NA; Wattage: NA; Weight: NA; Datasheet: Y:\MIS_DATABASE\DATASHEETS\ICS\MEMORY\W25Q80DVSS.PDF
U129 = TPS65988DJ_VQFN56: IC 2-PORT USB TYPE-C AND USB PD CONTROLLER WITH INTEGRATED POWER SWITCH VQFN56; Chkd/date: MANIRAJA/290721; Crtd /date: ALVY/280721; Custom_Duty: 15%; Customs_HS_Code: 85423100; Distributor_name: DIGIKEY; Distributor_part_number: 296-52068-1-ND; Footprint Path: Y:\MIS_DATABASE\Library\ALTIUM_TOOL\PCB_FOOTPRINTS\Altium_Footprint_Lib.PcbLib; Height: 1.00MM; Library Path: Y:\MIS_DATABASE\Library\ALTIUM_TOOL\SCHEMATICS_PARTS\MS_MISCPOWER_Library.schlib; Mfr_name: TEXAS INSTRUMENTS; Mistral Part No: 142021070017-R; Package: VQFN56; Part_type: ICS\POWER\MANAGEMENT; Project: TI_AM62x_SKEVM; RoHS: RoHS; Temperature: -10°C+75°C; Tolerance: NA; Voltage: NA; Wattage: NA; Weight: 127.6mg; Datasheet: Y:\MIS_DATABASE\DATASHEETS\ICS\POWER\TPS65988DHRSHR.PDF
U136 = AM275X_EVM_SOC_BGA361: IC AM275x EVM SoC BGA361; Chkd/date: PRADEEP/220524; Crtd /date: SHANKARI/210524; Custom_Duty: NA; Customs_HS_Code: NA; Distributor_name: NA; Distributor_part_number: NA; Height: 1.42MM; Library Ref: AM275x_EVM_SoC_BGA361; Mfr_name: NA; Mistral Part No: 141324050006; Package: BGA361; Part_type: ICS\DIGITAL\FPGA; Project: AM275x_EVM; Remarks: FP NEED TO CHECK WITH MANUFACTURE AND CUSTOMER; RoHS: NA; Temperature: NA; Tolerance: NA; Voltage: NA; Wattage: NA; Weight: NA; Datasheet: Y:\MIS_DATABASE\DATASHEETS\ICS\INTERFACE\AM275x_EVM_SoC.PDF
C787 C3659 C3660 = CAP: CAP CERAMIC 0.1uF 16V 5% X7R 0402; Chkd/date: VASANTHA/211215; Crtd /date: VASANTHA/211215; Custom_Duty: 15%; Customs_HS_Code: 85322990; Distributor_name: DIGIKEY; Distributor_part_number: 490-6327-1-ND; Footprint Path: Y:\MIS_DATABASE\Library\ALTIUM_TOOL\PCB_FOOTPRINTS\Altium_Footprint_Lib.PcbLib; Height: 0.55MM; Library Path: Y:\MIS_DATABASE\Library\ALTIUM_TOOL\SCHEMATICS_PARTS\MS_DISCRETE_Library.schlib; Mfr_name: MURATA; Mfr_part_number: GRM155R71C104JA88D; Mistral Part No: 120015120018-R; Package: 0402; Part_type: CAPACITORS\CERAMIC; Project: DLRL_NBSDR; RoHS: RoHS; Temperature: -55°C+125°C; Tolerance: 5%; Voltage: 16V; Wattage: NA; Weight: 6mg; Datasheet: Y:\MIS_DATABASE\DATASHEETS\CAPACITORS\MURATA-GXX-SER_NOV17.PDF
R558 R5811-R5819 = RESISTOR: RES 0E 1/10W JUMPER 0402; Chkd/date: VASANTHA/061216; Crtd /date: NAVEED/201014; Custom_Duty: 15%; Customs_HS_Code: 85332119; Distributor_name: DIGIKEY; Distributor_part_number: P0.0JCT-ND; Footprint Path: Y:\MIS_DATABASE\Library\ALTIUM_TOOL\PCB_FOOTPRINTS\Altium_Footprint_Lib.PcbLib; Height: 0.40MM; IBISSP_MODLES: VALUE REPEATING 2 TIME; Library Path: Y:\MIS_DATABASE\Library\ALTIUM_TOOL\SCHEMATICS_PARTS\MS_DISCRETE_Library.schlib; Mfr_name: PANASONIC-ECG; Mfr_part_number: ERJ-2GE0R00X; Mistral Part No: 110018030052-R; Package: 0402; Part_type: RESISTORS\FIXED; Project: AEGIS POM; RoHS: RoHS; SIGNAL_MODEL: RESISTOR_RES0402_0-5_0E_0E; Temperature: -55°C+155°C; Tolerance: NA; Voltage: NA; Wattage: 1/10W; Weight: 0.8mg; Datasheet: Y:\MIS_DATABASE\DATASHEETS\RESISTORS\PAN-ERJSER_NOV17.PDF
R3736 R5216 = RESISTOR: RES 1K 1/20W 5% 0201; Chkd/date: MANIRAJA/050517; Crtd /date: MANIRAJA/050517; Custom_Duty: 15%; Customs_HS_Code: 85332119; Distributor_name: DIGIKEY; Distributor_part_number: 311-1KNCT-ND; Footprint Path: Y:\MIS_DATABASE\Library\ALTIUM_TOOL\PCB_FOOTPRINTS\Altium_Footprint_Lib.PcbLib; Height: 0.26MM; Library Path: Y:\MIS_DATABASE\Library\ALTIUM_TOOL\SCHEMATICS_PARTS\MS_DISCRETE_Library.schlib; Mfr_name: YAGEO AMERICA; Mfr_part_number: RC0201JR-071KL; Mistral Part No: 110009030395-R; Package: 0201; Part_type: RESISTORS\FIXED; Project: GOLDEN-I LITE; RoHS: RoHS; Temperature: -55°C+125°C; Tolerance: 5%; Voltage: NA; Wattage: 1/20W; Weight: 0.17mg; Datasheet: Y:\MIS_DATABASE\DATASHEETS\RESISTORS\RCXXXXL-SER_MAR18.PDF
R5759 = RESISTOR: RES 100K 1/10W 5% 0402; Chkd/date: VASANTHA/291216; Crtd /date: GEETHA/190406; Custom_Duty: 15%; Customs_HS_Code: 85332119; Distributor_name: DIGIKEY; Distributor_part_number: P100KJCT-ND; Footprint Path: Y:\MIS_DATABASE\Library\ALTIUM_TOOL\PCB_FOOTPRINTS\Altium_Footprint_Lib.PcbLib; Height: 0.40MM; Library Path: Y:\MIS_DATABASE\Library\ALTIUM_TOOL\SCHEMATICS_PARTS\MS_DISCRETE_Library.schlib; Mfr_name: PANASONIC-ECG; Mfr_part_number: ERJ-2GEJ104X; Mistral Part No: 110009030177-R; Package: 0402; Part_type: RESISTORS\FIXED; Project: RED EYE; RoHS: RoHS; Temperature: -55°C+155°C; Tolerance: 5%; Voltage: NA; Wattage: 1/10W; Weight: 0.8mg; Datasheet: Y:\MIS_DATABASE\DATASHEETS\RESISTORS\PAN-ERJSER_NOV17.PDF
SW9 = SW2_CHS-01TA: SWITCH SLIDE 1POS SPST SMD; Chkd/date: MANIRAJA/031018; Crtd /date: MANIRAJA/031018; Custom_Duty: 24%; Customs_HS_Code: 85369090; Distributor_name: DIGIKEY; Distributor_part_number: CKN10538CT-ND; Footprint Path: Y:\MIS_DATABASE\Library\ALTIUM_TOOL\PCB_FOOTPRINTS\Altium_Footprint_Lib.PcbLib; Height: 2.30MM; Library Path: Y:\MIS_DATABASE\Library\ALTIUM_TOOL\SCHEMATICS_PARTS\MS_SWITCH_Library.schlib; Mfr_name: CK; Mistral Part No: 130018100003-R; Package: SMD; Part_type: ELECTRO-MECHANICAL\SWITCH; Project: TI_60GHz-AOP; RoHS: RoHS; Temperature: -40°C+85°C; Tolerance: NA; Voltage: NA; Wattage: NA; Weight: NA; Datasheet: Y:\MIS_DATABASE\DATASHEETS\MISC\SWITCHES\TDAXX-SER.PDF
U57 = TS3DDR3812RUAR_WQFN42: IC 12-CH 1:2 MUX/DEMUX SWITCH FOR DDR3 APPLICATION WQFN42; Chkd/date: MANIRAJA/250918; Crtd /date: ALVY/250918; Custom_Duty: 15%; Customs_HS_Code: 85423100; Distributor_name: DIGIKEY; Distributor_part_number: 296-28307-1-ND; Footprint Path: Y:\MIS_DATABASE\Library\ALTIUM_TOOL\PCB_FOOTPRINTS\Altium_Footprint_Lib.PcbLib; Height: 0.80MM; Library Path: Y:\MIS_DATABASE\Library\ALTIUM_TOOL\SCHEMATICS_PARTS\MS_COMBINATIONAL_Library.schlib; Mfr_name: TEXAS INSTRUMENTS; Mistral Part No: 141018090023-R; Package: WQFN42; Part_type: ICS\DIGITAL\COMBINATIONAL; Project: TI_J7ES_EVM_CP; RoHS: RoHS; Temperature: -40°C+85°C; Tolerance: NA; Voltage: NA; Wattage: NA; Weight: 54.8mg; Datasheet: Y:\MIS_DATABASE\DATASHEETS\ICS\DIGITAL\COMBINATIONAL\TS3DDR3812.PDF
C614 = CAP: CAP CERAMIC 22uF 10V 20% X5R AUTO 0603; Chkd/date: MANIRAJA/250221; Crtd /date: ALVY/240221; Custom_Duty: 15%; Customs_HS_Code: 85369090; Distributor_name: MOUSER; Distributor_part_number: 81-GRT188R61A226ME13; Footprint Path: Y:\MIS_DATABASE\Library\ALTIUM_TOOL\PCB_FOOTPRINTS\Altium_Footprint_Lib.PcbLib; Height: 1.00MM; Library Path: Y:\MIS_DATABASE\Library\ALTIUM_TOOL\SCHEMATICS_PARTS\MS_DISCRETE_Library.schlib; Mfr_name: MURATA; Mfr_part_number: GRT188R61A226ME13D; Mistral Part No: 120021020033-R; Package: 0603; Part_type: CAPACITORS\CERAMIC; Project: TI_DRA821 SK EVM BRD; RoHS: RoHS; Temperature: -55°C+85°C; Tolerance: 20%; Voltage: 10V; Wattage: NA; Weight: NA; Datasheet: Y:\MIS_DATABASE\DATASHEETS\CAPACITORS\GRT188R61A226ME13.PDF
C615 = CAP: CAP CERAMIC 120pF 50V 5% C0G(NP0) AUTO 0201; Chkd/date: MANIRAJA/311221; Crtd /date: ALVY/301221; Custom_Duty: 15%; Customs_HS_Code: 85322990; Distributor_name: MOUSER; Distributor_part_number: 81-GRT0335C1H121JA2D; Footprint Path: Y:\MIS_DATABASE\Library\ALTIUM_TOOL\PCB_FOOTPRINTS\Altium_Footprint_Lib.PcbLib; Height: 0.33MM; Library Path: Y:\MIS_DATABASE\Library\ALTIUM_TOOL\SCHEMATICS_PARTS\MS_DISCRETE_Library.schlib; Mfr_name: MURATA; Mfr_part_number: GRT0335C1H121JA02D; Mistral Part No: 120021120016-R; Package: 0201; Part_type: CAPACITORS\CERAMIC; Project: AM62Q_SKEVM_BRD; RoHS: RoHS; Temperature: -55°C+125°C; Tolerance: 5%; Voltage: 50V; Wattage: NA; Weight: 0.33mg; Datasheet: Y:\MIS_DATABASE\DATASHEETS\CAPACITORS\GRT0335C1H121JA02.PDF
C620 = CAP: CAP CERAMIC 4.7uF 25V 10% X6S 0603; Chkd/date: MANIRAJA/241018; Crtd /date: ALVY/241018; Custom_Duty: 15%; Customs_HS_Code: 85322990; Distributor_name: DIGIKEY; Distributor_part_number: 490-7199-1-ND; Footprint Path: Y:\MIS_DATABASE\Library\ALTIUM_TOOL\PCB_FOOTPRINTS\Altium_Footprint_Lib.PcbLib; Height: 1.00MM; Library Path: Y:\MIS_DATABASE\Library\ALTIUM_TOOL\SCHEMATICS_PARTS\MS_DISCRETE_Library.schlib; Mfr_name: MURATA; Mfr_part_number: GRM188C81E475KE11D; Mistral Part No: 120018100056-R; Package: 0603; Part_type: CAPACITORS\CERAMIC; Project: TI_J7ES_EVM_CP; RoHS: RoHS; Temperature: -55°C+105°C; Tolerance: 10%; Voltage: 25V; Wattage: NA; Weight: 6.3mg; Datasheet: Y:\MIS_DATABASE\DATASHEETS\CAPACITORS\GRM188C81E475KE11D.PDF
L11 = INDUCTOR: IND CHIP 0.47uH 3.2A 20% 0806; Chkd/date: MANIRAJA/281221; Crtd /date: ALVY/281221; Custom_Duty: 24%; Customs_HS_Code: 85437099; Distributor_name: DIGIKEY; Distributor_part_number: 490-18076-1-ND; Footprint Path: Y:\MIS_DATABASE\Library\ALTIUM_TOOL\PCB_FOOTPRINTS\Altium_Footprint_Lib.PcbLib; Height: 1.20MM; Library Path: Y:\MIS_DATABASE\Library\ALTIUM_TOOL\SCHEMATICS_PARTS\MS_DISCRETE_Library.schlib; Mfr_name: MURATA; Mfr_part_number: DFE201612PD-R47M=P2; Mistral Part No: 130021120008-R; Package: 0806; Project: AM62Q_SKEVM_BRD; RoHS: RoHS; Temperature: -40°C+125°C; Tolerance: 20%; Voltage: NA; Wattage: NA; Weight: 18.8mg; Datasheet: Y:\MIS_DATABASE\DATASHEETS\DISCRETES\INDUCTORS\DFE201612PD.PDF
R634 = RESISTOR: RES 316K 1/10W 1% 0402; Chkd/date: MAZHAR/110310; Crtd /date: MUDDU/080310; Custom_Duty: 15%; Customs_HS_Code: 85332119; Distributor_name: DIGIKEY; Distributor_part_number: P316KLCT-ND; Footprint Path: Y:\MIS_DATABASE\Library\ALTIUM_TOOL\PCB_FOOTPRINTS\Altium_Footprint_Lib.PcbLib; Height: 0.40MM; Library Path: Y:\MIS_DATABASE\Library\ALTIUM_TOOL\SCHEMATICS_PARTS\MS_DISCRETE_Library.schlib; Mfr_name: PANASONIC-ECG; Mfr_part_number: ERJ-2RKF3163X; Mistral Part No: 110010030027-R; Package: 0402; Part_type: RESISTORS\FIXED; Project: VME_DSP_SUITE; RoHS: RoHS; Temperature: -55°C+155°C; Tolerance: 1%; Voltage: NA; Wattage: 1/10W; Weight: 0.8mg; Datasheet: Y:\MIS_DATABASE\DATASHEETS\RESISTORS\PAN-ERJSER_NOV17.PDF
TP92 = TESTPOINT: TESTPOINT CIR 20 SMD; Chkd/date: SHREESHAIL/171006; Crtd /date: MAZHAR/171006; Custom_Duty: NA; Customs_HS_Code: NA; Distributor_name: NA; Distributor_part_number: NA; Footprint Path: Y:\MIS_DATABASE\Library\ALTIUM_TOOL\PCB_FOOTPRINTS\Altium_Footprint_Lib.PcbLib; Height: NA; Library Path: Y:\MIS_DATABASE\Library\ALTIUM_TOOL\SCHEMATICS_PARTS\MS_DISCRETE_Library.schlib; MECHANICAL 3D STEP FILE: NA; Manufacturer: LOCAL; Mfr_name: LOCAL; Mistral Part No: NA; Package: SMD; Project: BT MODULE_CSRBC04; RoHS: NA; Temperature: NA; Tolerance: NA; Voltage: NA; Wattage: NA; Weight: NA; Datasheet: NA
U127 = TPS62827DMQR_VSONHR6: IC 1A ADJ STEP-DOWN CONVERTER WITH 1% OUTPUT ACCURACY VSON-HR6; Chkd/date: ALVY/071021; Crtd /date: MANIRAJA/071021; Custom_Duty: 15%; Customs_HS_Code: 85423100; Distributor_name: NA; Distributor_part_number: NA; Footprint Path: Y:\MIS_DATABASE\Library\ALTIUM_TOOL\PCB_FOOTPRINTS\Altium_Footprint_Lib.PcbLib; Height: 1.00MM; Library Path: Y:\MIS_DATABASE\Library\ALTIUM_TOOL\SCHEMATICS_PARTS\MS_MISCPOWER_Library.schlib; Mfr_name: TEXAS INSTRUMENTS; Mistral Part No: 142021100006-R; Package: VSON-HR6; Part_type: ICS\POWER\DC-DC CONVERTER; Project: TI_AM62x SKEVM_BRD; RoHS: RoHS; Temperature: -40°C+125°C; Tolerance: NA; Voltage: NA; Wattage: NA; Weight: NA; Datasheet: Y:\MIS_DATABASE\DATASHEETS\ICS\POWER\TPS6282XX-DEC2020.PDF

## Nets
DGND: C292.2 C301.2 C303.2 C305.2 C306.2 C307.2 C309.2 C312.2 C319.1 C320.1 C321.2 C322.2 C323.2 C324.2 C325.2 C614.2 C616.2 C620.2 C631.2 C641.2 C642.2 C643.2 C644.2 C787.2 C3659.2 C3660.2 J21.2 J21.10 R632.2 R662.2 R681.2 R682.2 R3736.2 R5216.1 U57.43(GND) U69.4(GND) U127.4(GND) U129.20(GND) U129.51(GND) U129.59(GND) ; also on sheet 13 14 15 16 17 18 19 20 21 22 23 24 25 26 27 28 29 31 32 33 34 35 36 37 38 39 40 41 42 43 44 45 46 47 48 49 50 51 52 53 54 55 56
VBUS_TYPEC1: C321.1 C641.1 C643.1 U129.13(VBUS1) ; also on sheet 13 16
VBUS_TYPEC2: C325.1 C642.1 C644.1 U129.3(VBUS2) ; also on sheet 16 37
VCC2V5_PG: R637.1 U127.2(PG)
VCC_3V3_SYS: C787.1 C3659.1 C3660.1 R645.1 R5215.1 R5759.2 R5777.1 U57.1(VCC) U57.17(VCC) U57.30(VCC) ; also on sheet 16 17 23 28 29 31 34 35 36 38 40 44 47 48 49 50 55 56
VCC_5V0: C620.1 R665.1 U127.6(VIN) ; also on sheet 14 15 16 18 37 42 43 45
VDD_2V5: C614.1 C615.1 C616.1 L11.2 R634.1 R637.2 TP92.1(TP) ; also on sheet 35 36
ADCIN1: R679.2 R681.1 U129.6(ADCIN1)
ADCIN2: R678.2 R682.1 U129.10(ADCIN2)
DRAIN1: U129.8(DRAIN1_1) U129.15(DRAIN1_2) U129.19(DRAIN1_3) U129.58(DRAIN1_4)
DRAIN2: U129.7(DRAIN2_1) U129.52(DRAIN2_2) U129.56(DRAIN2_3) U129.57(DRAIN2_4)
eMMC_CLK: U57.42(C0) ; also on sheet 28
eMMC_CMD: U57.22(C9) ; also on sheet 28
eMMC_D0: U57.37(C2) ; also on sheet 28
eMMC_D1: U57.35(C3) ; also on sheet 28
eMMC_D2: U57.28(C6) ; also on sheet 28
eMMC_D3: U57.40(C1) ; also on sheet 28
eMMC_D4: U57.24(C8) ; also on sheet 28
eMMC_D5: U57.26(C7) ; also on sheet 28
eMMC_D6: U57.33(C4) ; also on sheet 28
eMMC_D7: U57.31(C5) ; also on sheet 28
LDO_1V8: C303.1 U129.35(LDO_1V8)
LDO_3V3: C292.1 C319.2 R374.1 R378.1 R644.1 R646.1 R658.1 R660.1 R664.1 R678.1 R679.1 U69.8(VCC) U129.9(LDO_3V3) ; also on sheet 13
MMC0_CLK: R558.1 U57.2(A0)
MMC0_FET_EN: R5215.2 R5216.2 U57.8(EN) ; also on sheet 47
MMC0_SEL_3V3: R5758.1 ; also on sheet 23
P2_PP_EXT_ENABLE: U129.49(GPIO17/PP_EXT2) ; also on sheet 37
PD_GPIO0: R674.2 U129.16(GPIO0)
PD_HRESET: C301.1 R662.1 U129.44(HRESET)
PD_I2C_IRQ: R645.2 R655.1 ; also on sheet 47
PD_MS_I2C1_IRQ: R660.2 U129.29(~{I2C1_IRQ})
PD_MS_I2C1_SCL: R633.1 R664.2 U129.27(I2C1_SCL)
PD_MS_I2C1_SDA: R627.1 R658.2 U129.28(I2C1_SDA)
PD_S_I2C2_IRQ: R655.2 U129.34(~{I2C2_IRQ})
PD_S_I2C2_SCL: R657.2 U129.32(I2C2_SCL)
PD_S_I2C2_SDA: R656.2 U129.33(I2C2_SDA)
PD_SPI_CLK: J21.7 R652.2 U69.6(CLK)
PD_SPI_MISO: J21.5 R644.2 R654.2 U69.2(DO(IO1))
PD_SPI_MOSI: J21.8 R653.2 U69.5(DI(IO0))
PD_SPI_SS: J21.9 R646.2 R651.2 U69.1(~{CS})
PD_VIN_3V3: C320.2 U129.5(VIN_3V3)
PORT1_15W: R386.1 ; also on sheet 13
PORT2_15W: R390.1 ; also on sheet 13
PP1_CABLE: C309.1 U129.25(PP1_CABLE)
PP2_CABLE: C631.1 R665.2 U129.46(PP2_CABLE)
SD_MMC0_CLK: U57.41(B0) ; also on sheet 29
SD_MMC0_CMD: U57.23(B9) ; also on sheet 29
SD_MMC0_D0: U57.38(B2) ; also on sheet 29
SD_MMC0_D1: U57.36(B3) ; also on sheet 29
SD_MMC0_D2: U57.29(B6) ; also on sheet 29
SD_MMC0_D3: U57.39(B1) ; also on sheet 29
SoC_I2C0_SCL: R657.1 ; also on sheet 35 36 47 48 49 50 55
SoC_I2C0_SDA: R656.1 ; also on sheet 35 36 47 48 49 50 55
SOC_MMC0_CLK: R558.2 U136.V5(MMC0_CLK)
SOC_MMC0_CMD: R5819.1 U57.14(A9)
SOC_MMC0_CMD_R: R5819.2 U136.T6(MMC0_CMD)
SOC_MMC0_DAT0: R5811.1 U57.4(A2)
SOC_MMC0_DAT0_R: R5811.2 U136.W4(MMC0_DAT0)
SOC_MMC0_DAT1: R5812.1 U57.5(A3)
SOC_MMC0_DAT1_R: R5812.2 U136.W5(MMC0_DAT1)
SOC_MMC0_DAT2: R5813.1 U57.11(A6)
SOC_MMC0_DAT2_R: R5813.2 U136.V6(MMC0_DAT2)
SOC_MMC0_DAT3: R5814.1 U57.3(A1)
SOC_MMC0_DAT3_R: R5814.2 U136.U6(MMC0_DAT3)
SOC_MMC0_DAT4: R5815.1 U57.13(A8)
SOC_MMC0_DAT4_R: R5815.2 U136.U7(MMC0_DAT4)
SOC_MMC0_DAT5: R5816.1 U57.12(A7)
SOC_MMC0_DAT5_R: R5816.2 U136.T7(MMC0_DAT5)
SOC_MMC0_DAT6: R5817.1 U57.6(A4)
SOC_MMC0_DAT6_R: R5817.2 U136.V7(MMC0_DAT6)
SOC_MMC0_DAT7: R5818.1 U57.7(A5)
SOC_MMC0_DAT7_R: R5818.2 U136.W7(MMC0_DAT7)
SoC_USB0_DRVVBUS_3V3: R674.1 ; also on sheet 23 37
SPI_HOLDn: R374.2 U69.7(~{HOLD}(IO3))
SPI_WPn: R378.2 U69.3(~{WP}(IO2))
SW_2V5: L11.1 U127.5(SW)
USBC_CONN1_CC1: C307.1 U129.24(C1_CC1) ; also on sheet 13
USBC_CONN1_CC2: C306.1 U129.26(C1_CC2) ; also on sheet 13
USBC_CONN2_CC1: C305.1 U129.45(C2_CC1) ; also on sheet 37
USBC_CONN2_CC2: C312.1 U129.47(C2_CC2) ; also on sheet 37
VMAIN_PD: C322.1 C323.1 C324.1 U129.1(PP_HV2) U129.11(PP_HV1) ; also on sheet 13
N17824845: R654.1 U129.36(SPI_MISO/GPIO8)
N17824852: R653.1 U129.37(SPI_MOSI/GPIO9)
N17824859: R652.1 U129.38(SPI_CLK/GPIO10)
N17824866: R651.1 U129.39(~{SPI_SS}/GPIO11)
N19741013: R390.2 U129.18(GPIO2)
N22682556: J21.1 R633.2
N22682559: J21.3 R627.2
N26271323: R386.2 U129.17(GPIO1)
N29438875: C615.2 R632.1 R634.2 U127.3(FB)
N29438936: R5777.2 U127.1(EN)
N29440900: R5758.2 R5759.1 SW9.2 U57.9(SEL1) U57.10(SEL2)
N29441393: R3736.1 SW9.1

Not connected (* = marked no-connect by the designer): J21 4* 6*; U57 15(A10)* 16(A11)* 18(C11)* 19(B11)* 20(C10)* 21(B10)* 25(B8)* 27(B7)* 32(B5)* 34(B4)*; U129 21(I2C3_SCL/GPIO5)* 22(I2C3_SDA/GPIO6)* 23(~{I2C3_IRQ}/GPIO7)* 30(HPD1/GPIO3)* 31(HPD2/GPIO4)* 40(GPIO12)* 41(GPIO13)* 42(GPIO14/PWM)* 43(GPIO15/PWM)* 48(GPIO16/PP_EXT1)* 50(C1_USB_P/GPIO18)* 53(C1_USB_N/GPIO19)* 54(C2_USB_P/GPIO20)* 55(C2_USB_N/GPIO21)*

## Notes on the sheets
sheet 1
- POWER SUPPLY (CORE) FOR ETHERNET PHY
- 2.5V (ETHERNET PHY), 1.0AMPS SUPPLY
- SILK SCREEN : VDD_2V5
sheet 2
- MMC0 INTERFACE
- 0E provision on MMC0_CLK
  Recommended for signal integrity
- MMC0 INTERFACE FET SELECTION
- 1:2
  FET
- MMC0_SEL_3V3
- MMC0
- 0
- uSD interface
- 1
- EMMC interface
sheet 3
- AM275x EVM
- TABLE OF CONTENTS
- TABLE OF CONTENTS
- PAGE
- CONTENTS
- PAGE
- CONTENTS
- BOARD REVISION
- E1
- 01
- TABLE OF CONTENTS
- 42
- AUDIO - MICROPHONE/LINE IN 2
- SCHEMATIC VERSION
- 1.0
- 02
- REVISION HISTORY
- 43
- AUDIO EXPANSION CONNECTOR 1 & DECAPS
- 03
- LINK TO DESIGN COLLATERALS AND FAQs
- AUDIO EXPANSION CONNECTOR 2 & DECAPS
- 44
- 04
- BLOCK DIAGRAM AM275x EVM
- 45
- CAN TRANSCEIVER
- 05
- BLOCK DIAGRAM XDS110 DEBUGGER
- 46
- BOOTMODE IO EXPANDER AND BUFFERS
- 06
- POWER ARCHITECTURE BLOCK DIAGRAM
- 47
- IO EXPANDER AND USER TEST LEDS
- 07
- POWER SEQUENCE
- 48
- TEMPERATURE SENSOR AND BOARD ID EEPROM
- 08
- I2C TREE
- 49
- CURRENT MONITORING DEVICES 1
- 09
- GPIO MAPPING TABLE
- 50
- CURRENT MONITORING DEVICES 2
- 10
- USB TYPE-C POWER
- 51
- FT4232 UART TO USB BRIDGE
- 11
- USB TYPE-C POWER CONNECTOR
- 52
- FT4232 UART BUFFERS
- 12
- PERIPHERAL POWER SUPPLY
- XDS110 DEBUGGER
- 53
- 13
- PRE REGULATOR SUPPLIES - LDOs
- 54
- XDS110 JTAG BUFFER
- 14
- SOC POWER SUPPLY PMIC - 1
- XDS110 TEST AUTOMATION BUFFERS
- 55
- 15
- SOC POWER SUPPLY PMIC - 2
- 56
- JTAG 20 PIN cTI CONNECTOR
- 16
- SOC POWER SUPPLIES, SUPPLY RAILS AND SOC GROUND VSS
- 57
- ASSEMBLY NOTES AND MOUNTING HARDWARE
- 17
- SOC POWER SUPPLIES - DECAPS 1
- 18
- SOC POWER SUPPLIES - DECAPS 2
- SOC WKUP /MCU DOMAIN & OSCILLATOR
- 19
- 20
- CDCE CLOCK GENERATION, SOC & ETHERNET PHY CLOCK BUFFER
- SOC RESET -1
- 21
- 22
- SOC RESET -2
- Note:
  Verify the DNI components configuration with respect to
  the EVM schematics (Use PDF) after  completion of design
  before board assembly
- 23
- BOOT MODE SWITCHES & BOOTMODE PINS
- 24
- HYPERRAM DEVICE INTERFACE AND RESET
- 25
- SOC OSPI INTERFACE AND OSPI DEVICE INTERFACE & RESET
- 26
- SOC MMC0 INTERFACE AND FET SELECTION
- 27
- eMMC FLASH + RESET
- 28
- SD CARD - LOAD SWITCH, LOAD SWITCH RESET LOGIC
- 29
- SOC PERIPHERALS 1 - McASP
- 30
- SOC PERIPHERALS 2 - GENERAL
- 31
- SOC PERIPHERAL 3 - ETHERNET INTERFACE AND USB
- McASP4 FET SELECTION AND MLB HEADER
- 32
- 33
- SoC ADC0 INTERFACE AND HEADER
- AUDIO REFERENCE CLOCKS
- 34
- 34
- 35
- 35
- Ethernet PHY power supply (VDD_2V5)
- CPSW3G RGMII_1 ETHERNET CONNECTOR 1 & RESET
- 36
- 37
- CPSW3G RGMII_2 ETHERNET CONNECTOR 2 & RESET
- 38
- USB0 TYPE-C DRP
- 39
- AUDIO - STEREO LINEOUT - 1
- 40
- AUDIO - STEREO LINEOUT - 2
- 41
- AUDIO - MICROPHONE/LINE IN 1
sheet 4
- REVISION HISTORY
- VER #
- DATE
- DESCRIPTION OF CHANGES
- AUTHOR
- REVIEWED  BY
- APPROVED  BY
- 0.1
- 28-05-2024
- Initial Draft
- 0.2
- 05-06-2024
- Internally reviewed and comments updated
- Venkatesh K J
- Pandiyarajan
- 0.3
- 06-06-2024
- Modified PMIC section as per TI requirements
- Venkatesh K J
- Pandiyarajan
- 0.4
- 12-06-2024
- Implemented review comments from TI
- Venkatesh K J
- Pandiyarajan
- 0.5
- 20-06-2024
- Implemented review comments from TI
  1. Updated I2C address of PMIC
  2. Resetstatz for warm reset control
- Venkatesh K J
- Pandiyarajan
- 0.6
- 26-06-2024
- Implemented review comments from TI
  1.Current sensing for VDD_CANUART AND VDDSHV_CANUART
  2. Decap under BGA package change from 0402 to 0201
- Venkatesh K J
- Pandiyarajan
- 0.7
- 19-07-2024
- Implemented reiew comments form TI
  1. Implemention of SYNC1_OUT function
  2. Addition of OR logic for 1V8/3V3 IO voltage control of MMC0
  3. PMIC OPN changed to TPS6522435RAHRQ1
- Venkatesh K J
- Pandiyarajan
- Implemented review comments from TI
  1. Added optional routing path for CS in OSPI devices having  CS on A3 rather than C2.
  2. Changed PCM audio device input cap from 2.2uf to 22uf
- 0.8
- 09-08-2024
- Venkatesh K J
- Pandiyarajan
- 0.9
- 20-08-2024
- Updated VDD_CORE decaps with alternate MPN based on TI PDN suggestion.
- Venkatesh K J
- Pandiyarajan
- 1. Capacitor line items optimized to reuse VDD_CORE decap values.
  2. Schematic Baselined
- 1.0
- 28-08-2024
- Venkatesh K J
- Pandiyarajan
sheet 5
- LINK TO DESIGN COLLATERALS
- https://e2e.ti.com/support/processors-group/processors/f/processors-forum/1285107/faq-am64x-
  am62x-am62ax-custom-board-hardware-design---collaterals-for-reference-during-schematic-design-and-schematics-review
- FAQs
sheet 6
- BLOCK DIAGRAM AM275x EVM
sheet 7
- BLOCK DIAGRAM_XDS110
sheet 8
- POWER ARCHITECTURE BLOCK DIAGRAM
sheet 9
- POWER  UP SEQUENCE
- POWER DOWN SEQUENCE
- TO BE UPDATED !
sheet 10
- I2C TREE
sheet 11
- GPIO MAPPING TABLE
sheet 12
- USB TYPE-C POWER
- TYPE-C DUAL PD CONTROLLER
- BP_NoWait
  Safe Configuration
- I2C Slave
   Address
- Port1
- Port2
- I2C2(Default)
- 0x38
- 0x3F
- SPI EEPROM & PROGRAMMING HEADER
- I2C1
- 0x20
- 0x24
